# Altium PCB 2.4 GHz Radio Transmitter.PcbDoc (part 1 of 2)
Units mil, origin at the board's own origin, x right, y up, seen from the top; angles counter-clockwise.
Board outline 5905.26 x 4050.27 mil, 4 copper layers (Top Layer, GND, Power, Bottom Layer), stack 63.355 mil thick; 215 components, 108 nets, 659 pads, 107 vias.
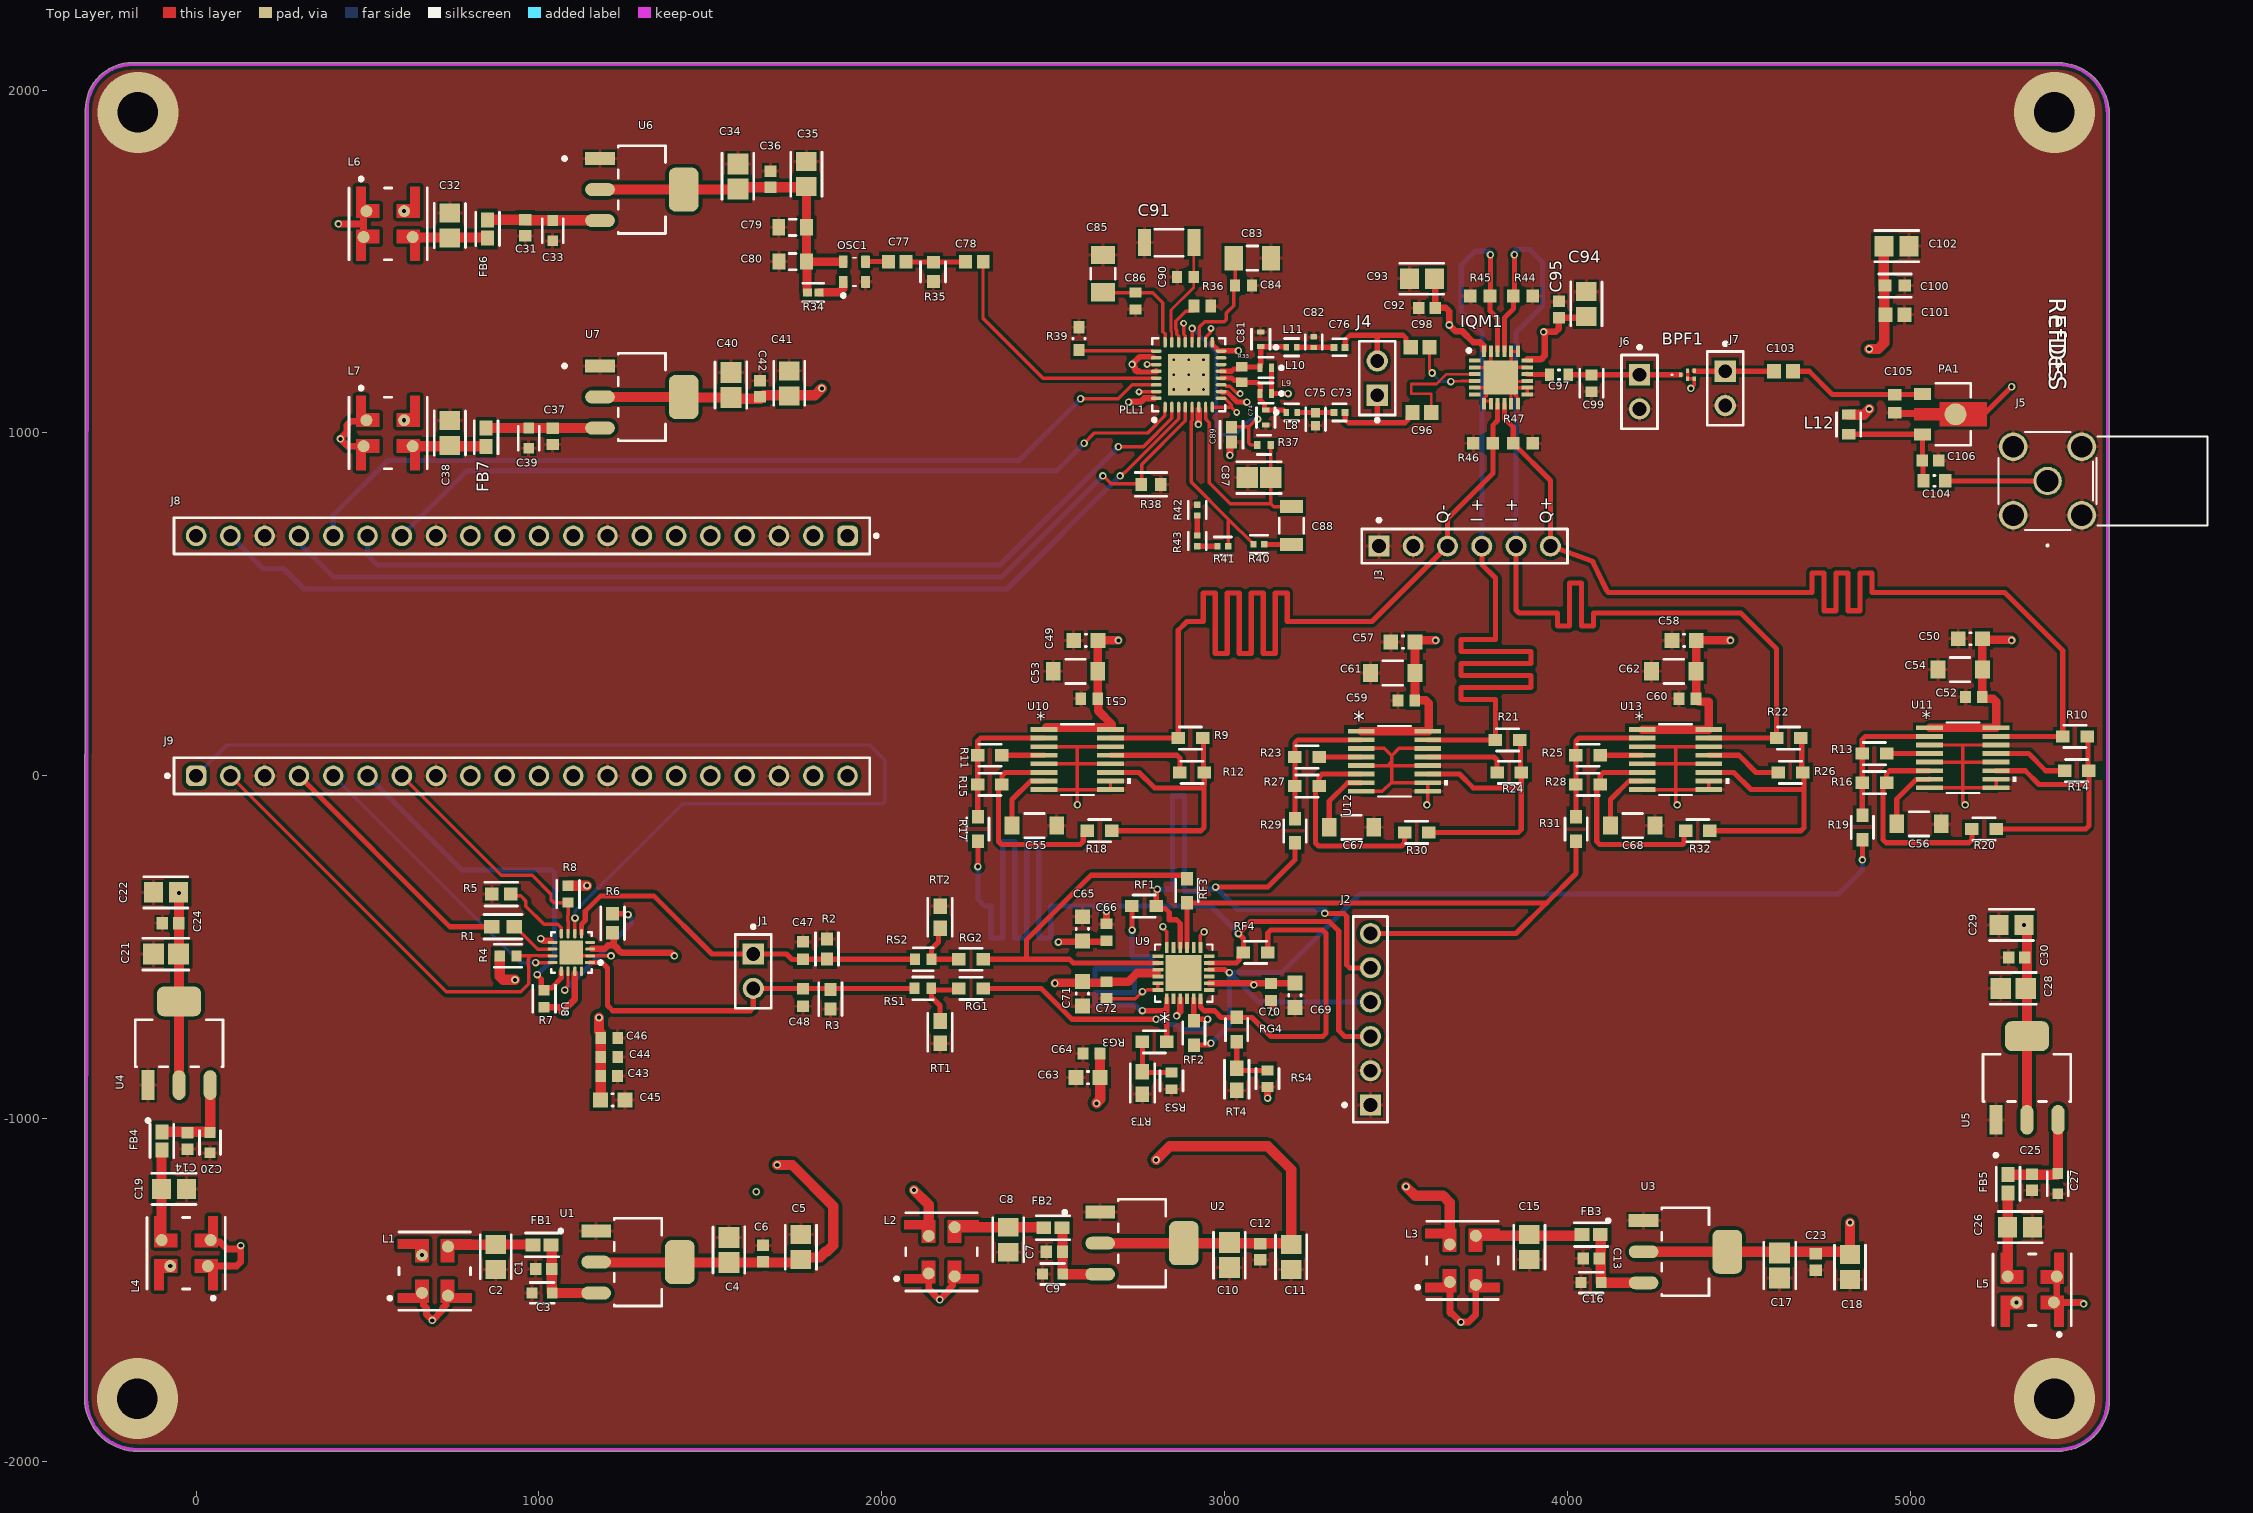
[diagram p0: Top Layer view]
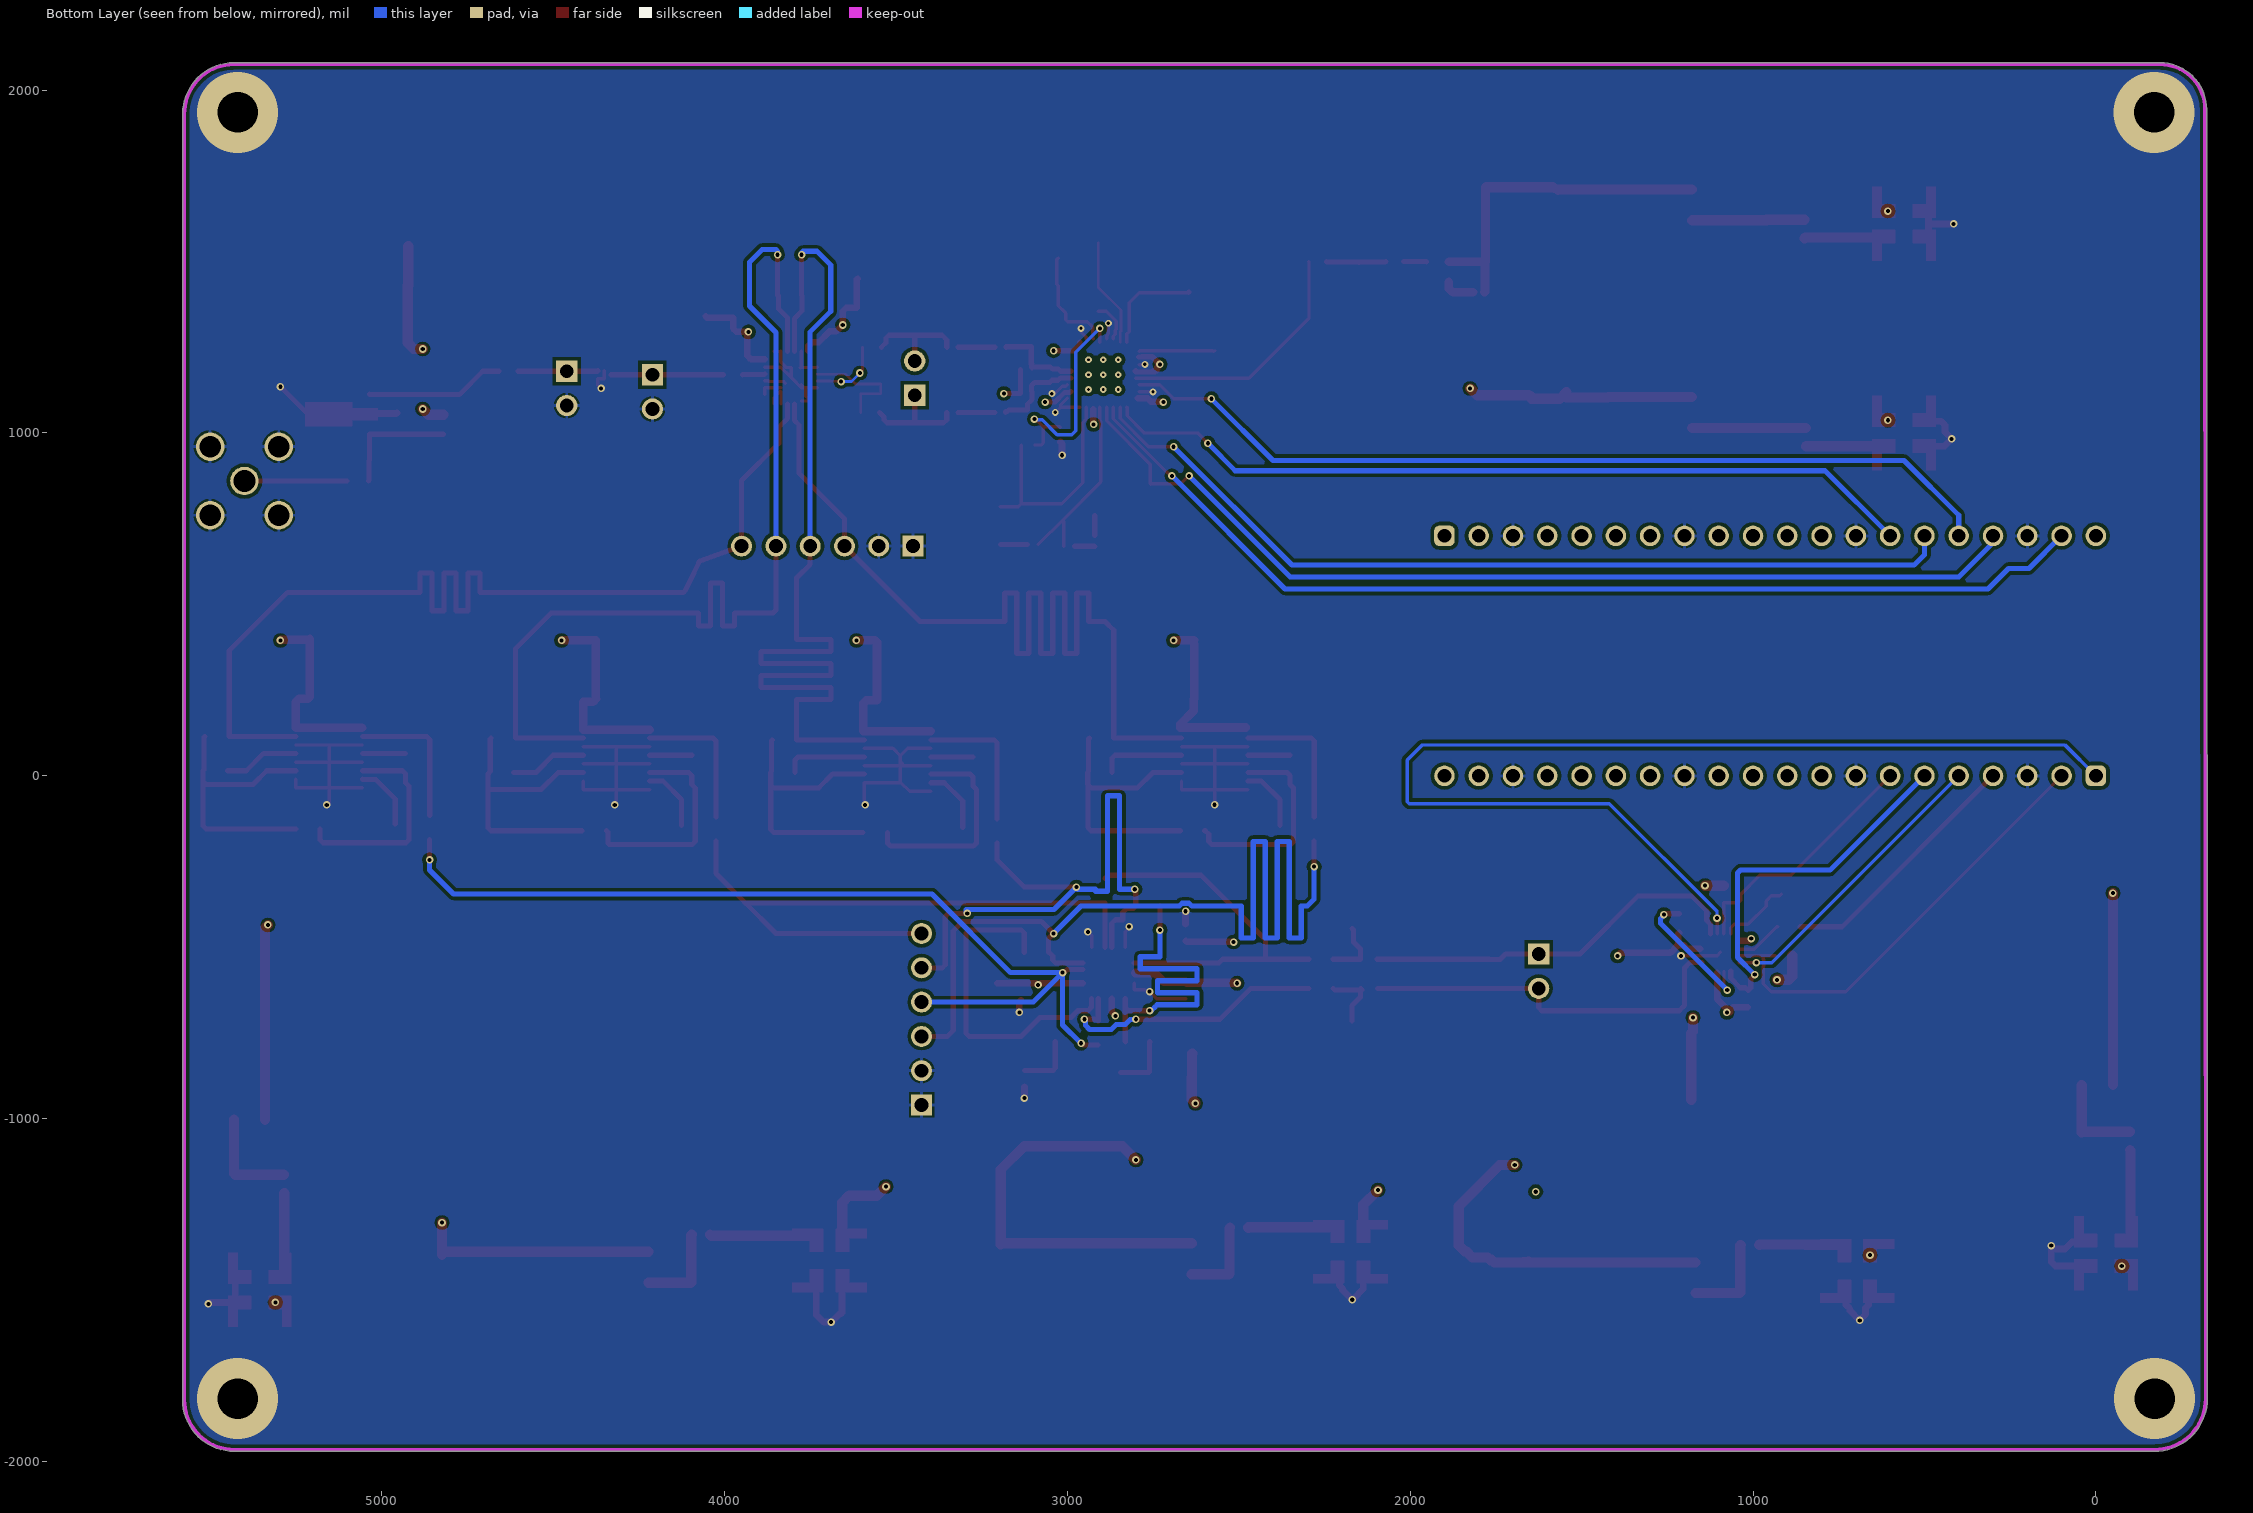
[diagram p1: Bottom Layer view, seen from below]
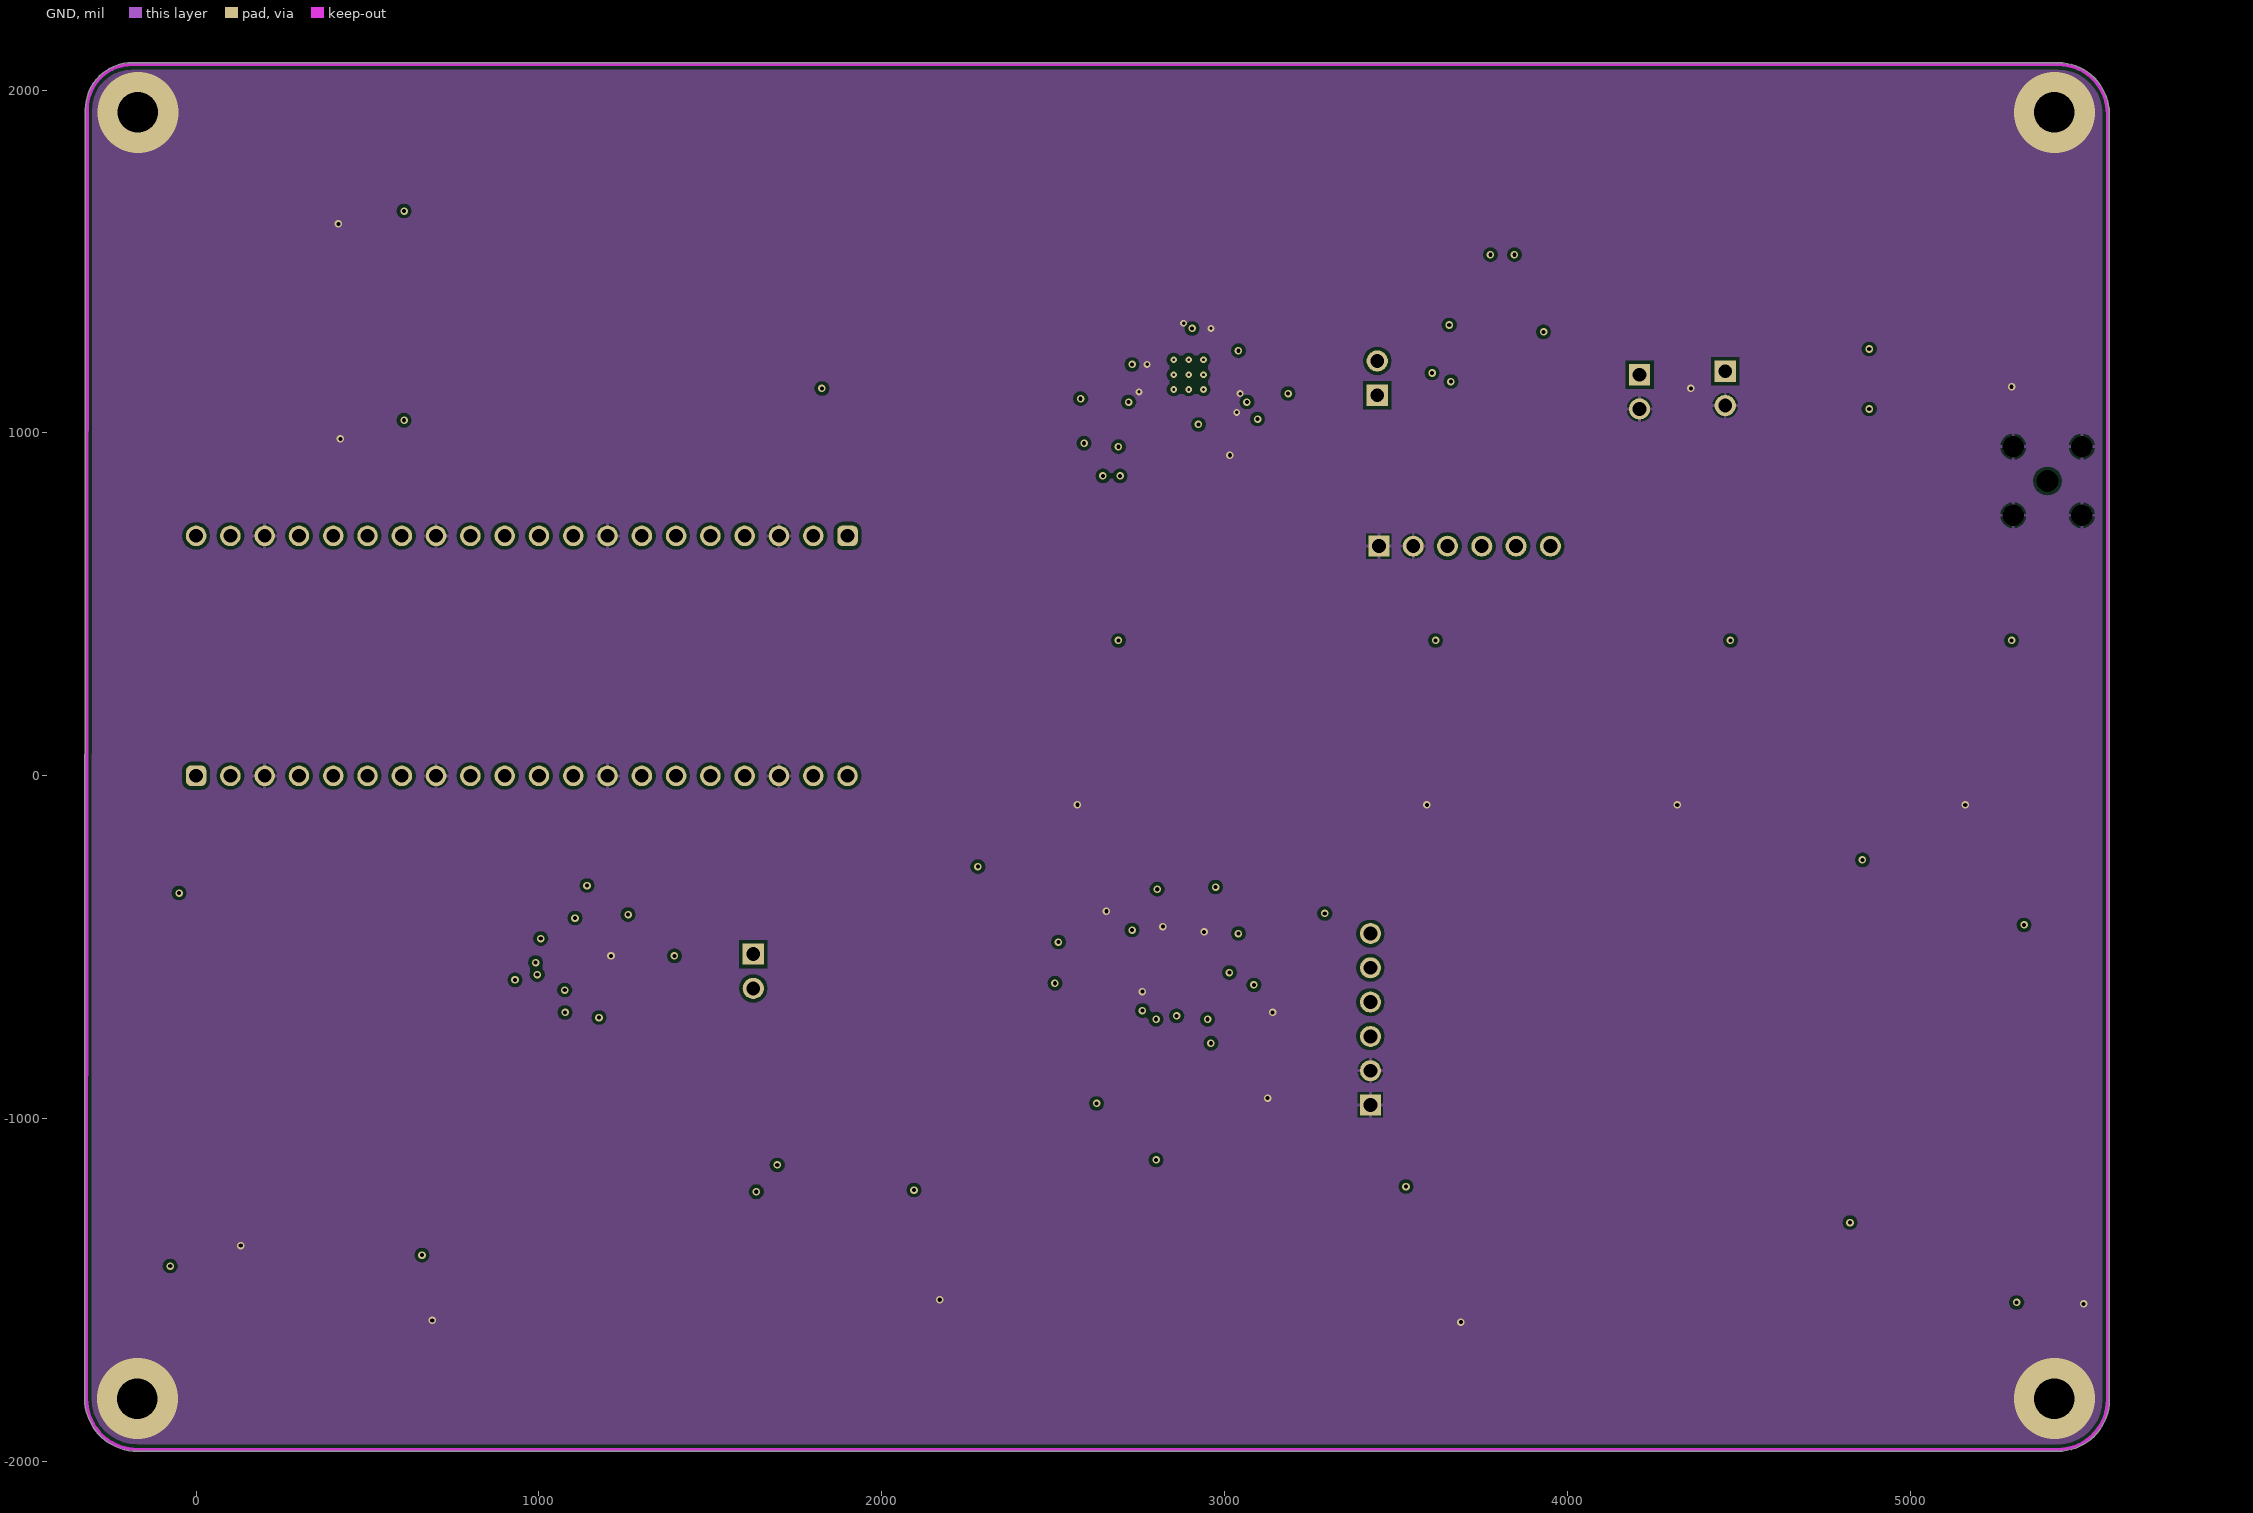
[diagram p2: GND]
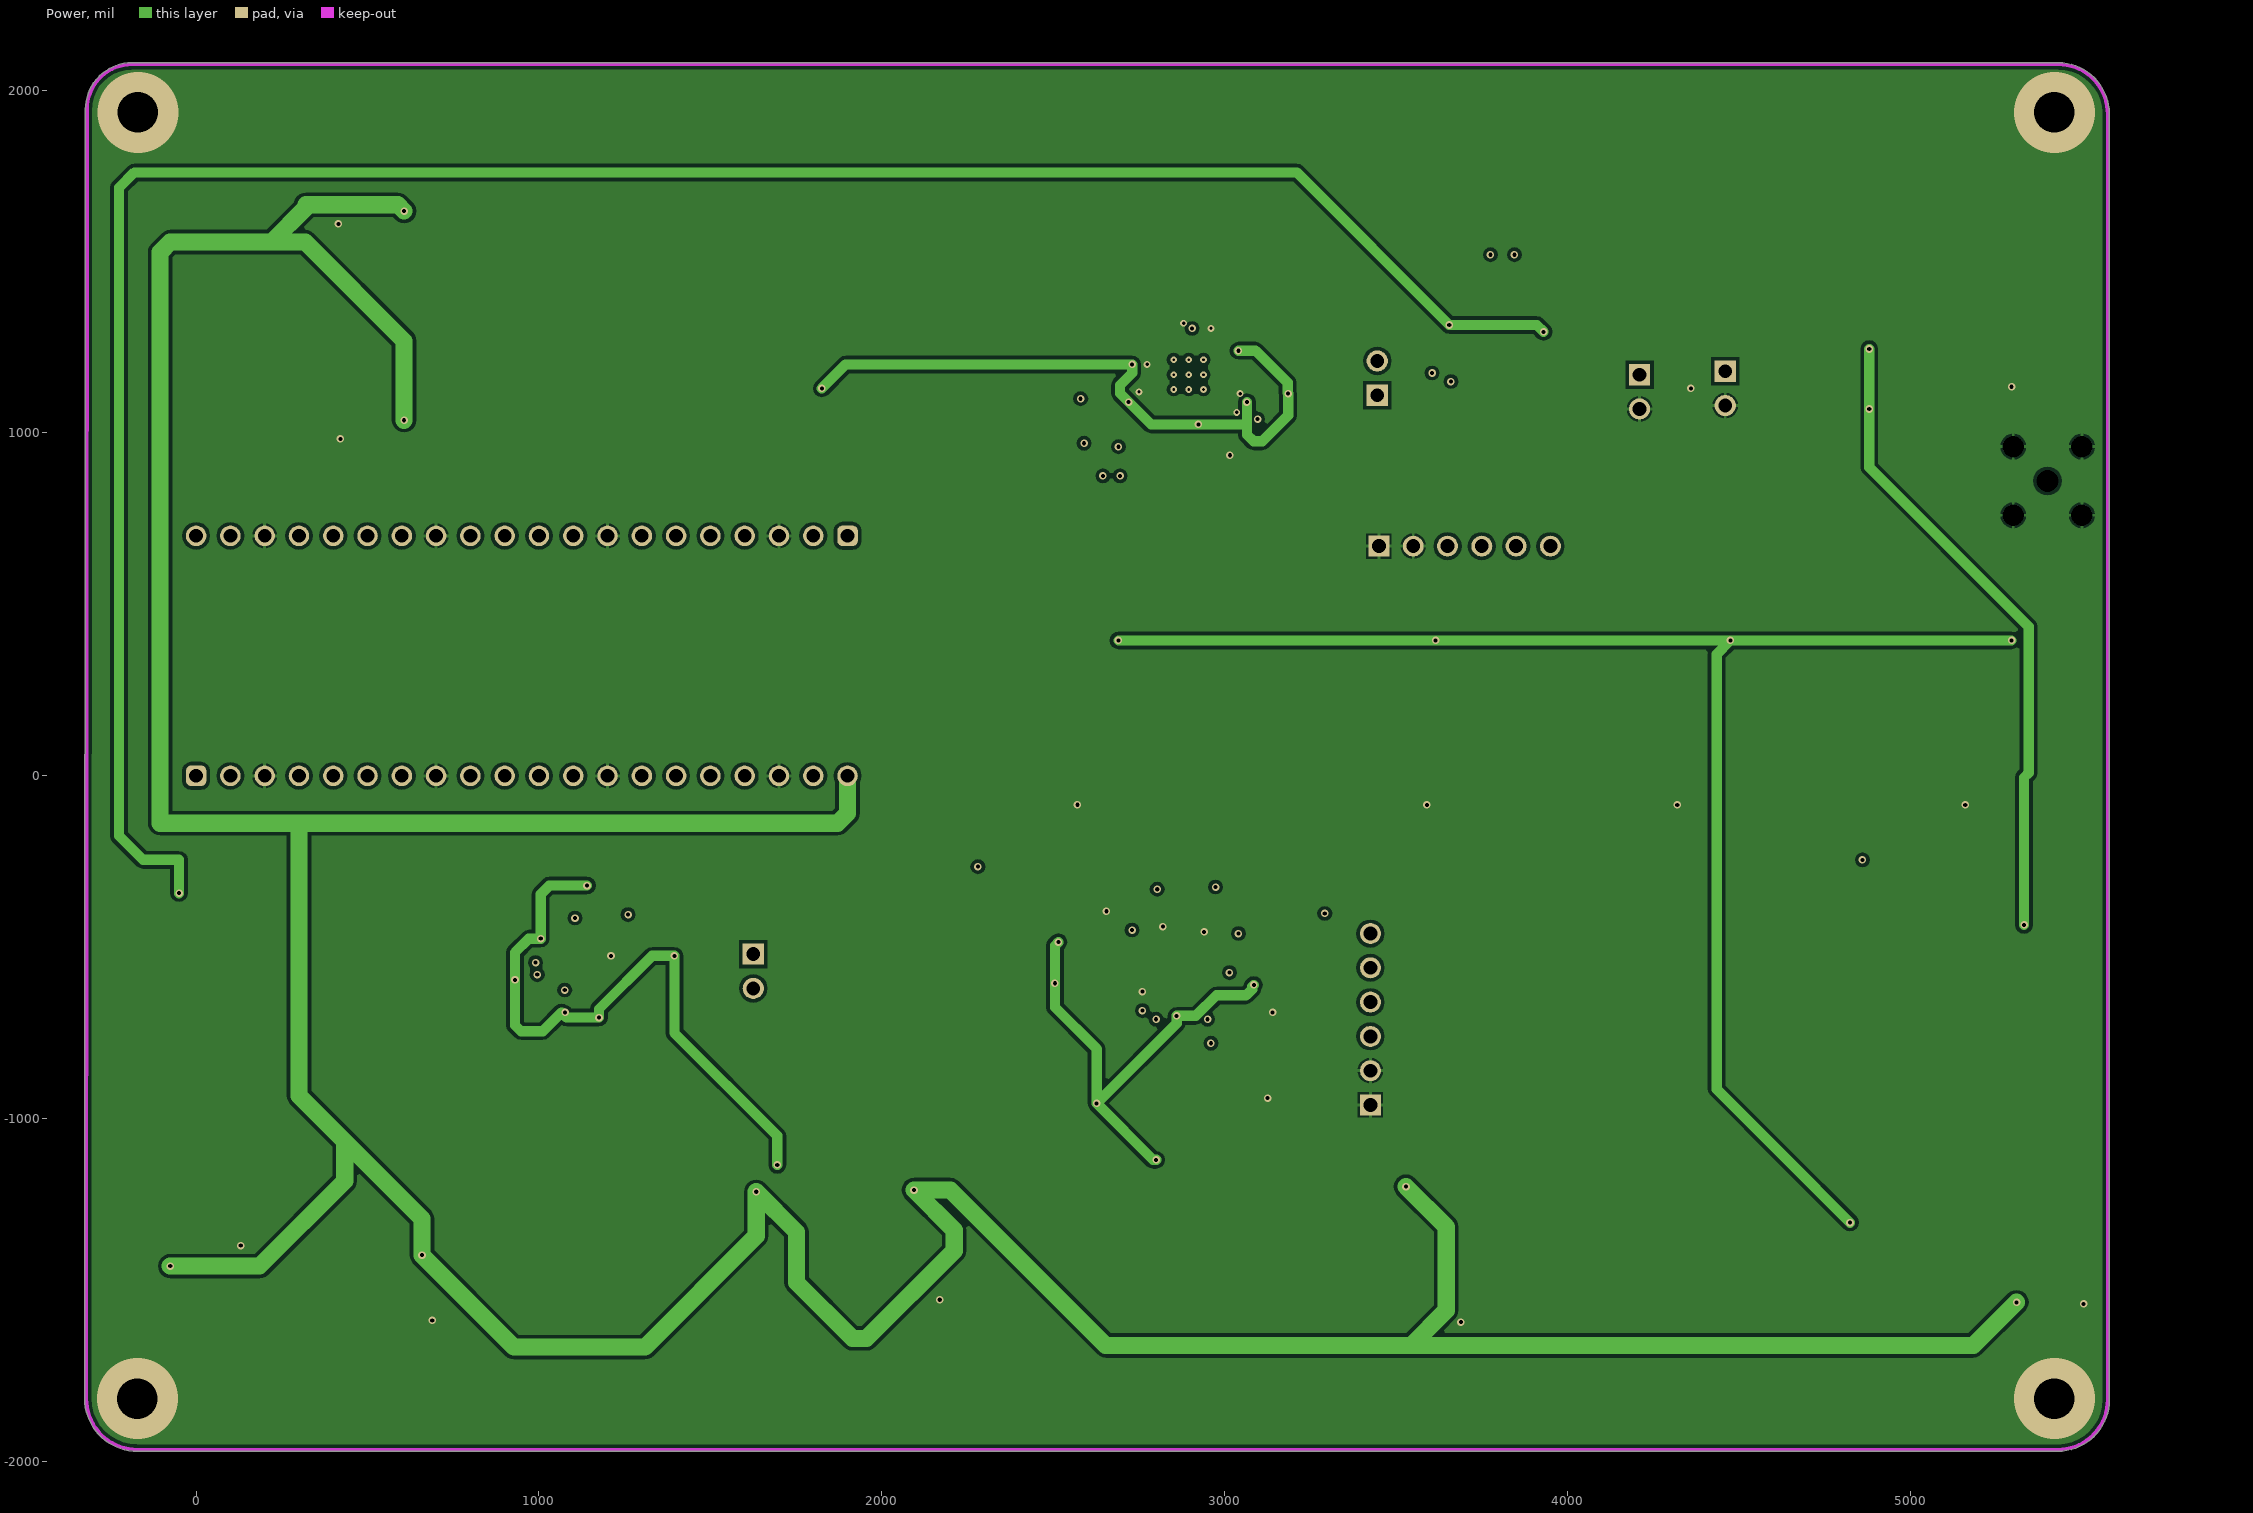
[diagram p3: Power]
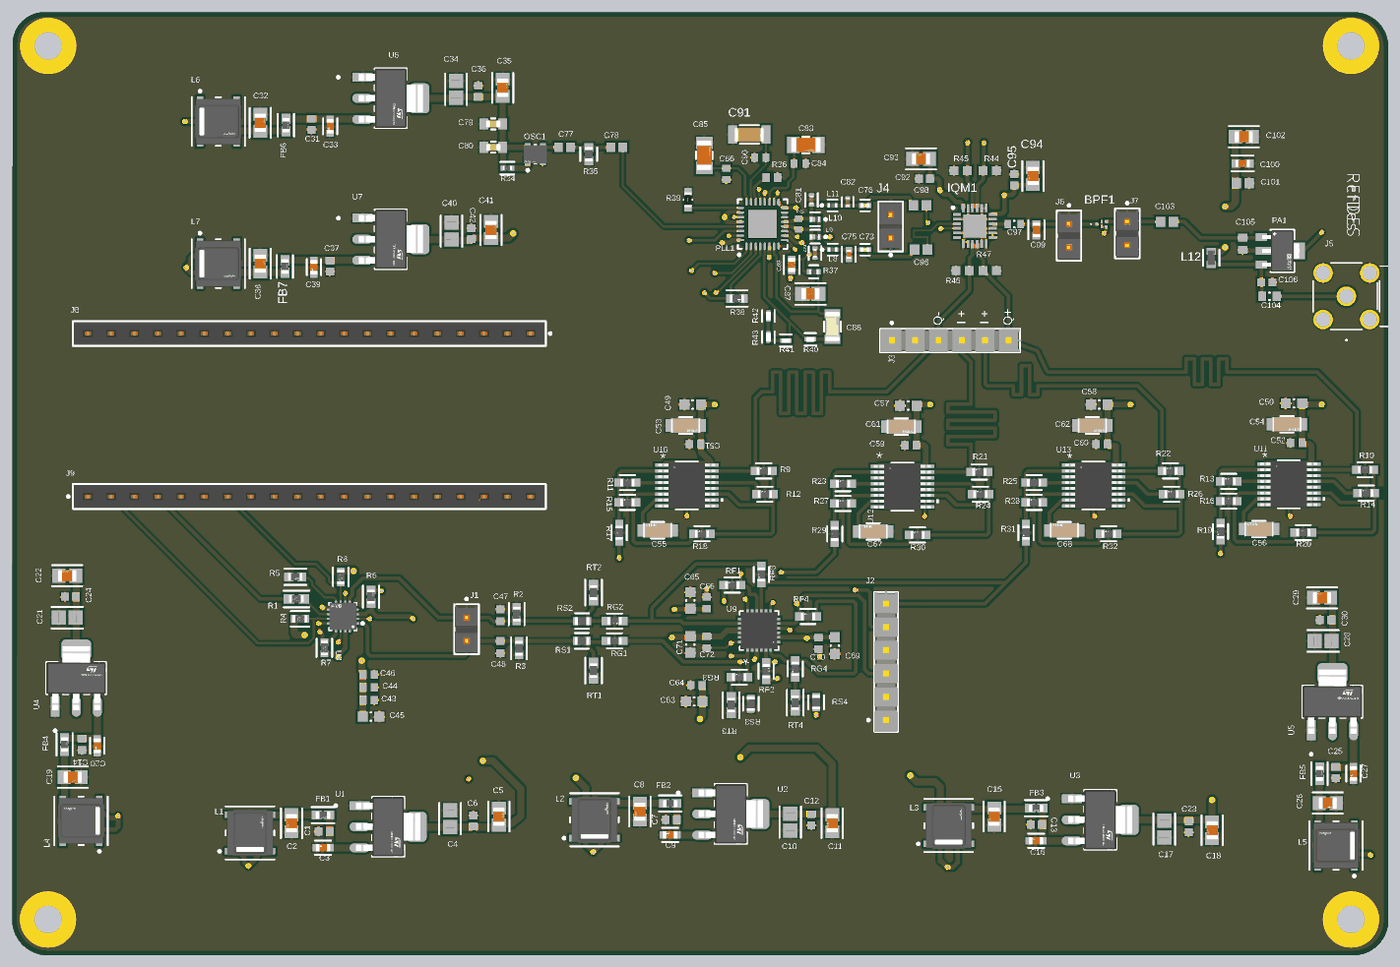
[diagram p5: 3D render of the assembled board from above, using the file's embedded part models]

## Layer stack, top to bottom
Top Solder: solder mask 1, Solder Resist, Dk 3.6
Top Layer: signal copper 1.378
Dielectric 1: prepreg 7.957, FR-4, Dk 3.61
GND: signal copper 1.378
Core: core 41.929, FR-4, Dk 4.4
Power: signal copper 1.378
Dielectric 2: prepreg 7.957, FR-4, Dk 3.61
Bottom Layer: signal copper 1.378
Bottom Solder: solder mask 1, Solder Resist, Dk 3.6

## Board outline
-325.02,-1816.32 -322.69,1944.12 cw(c-186.81,1944.11) -186.81,2080 5431.44,2080.02 5431.46,2080.01 cw(c5430.72,1930.72) 5580.02,1930.72 5580.04,1930 5580.25,-1819.6 cw(c5429.83,-1819.6) 5429.83,-1970.01 -171.08,-1970.26 cw(c-171.08,-1816.32)

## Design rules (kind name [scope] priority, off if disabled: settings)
BoardOutlineClearance [All] p1: gap=15 ignorepadtopadclearanceinfootprint=FALSE
Clearance "Clearance Polygons" [InPolygon] p1: gap=10 ignorepadtopadclearanceinfootprint=FALSE
Clearance [All] p2: gap=5 ignorepadtopadclearanceinfootprint=FALSE
ComponentClearance "HM-TRP & UFL" [InComponent('X1') vs InComponent('U1')] p1: gap=0 collisioncheckmode=3 verticalgap=0 showdistances=FALSE
ComponentClearance [All] p2: gap=1 collisioncheckmode=3 verticalgap=1 showdistances=FALSE
DiffPairsRouting [All] p1: maxlimit=393.7 minlimit=5 mostfreqgap=8 toplayer_minwidth=5 toplayer_maxwidth=15 toplayer_prefwidth=8 midlayer1_minwidth=5 midlayer1_maxwidth=15 midlayer1_prefwidth=8 midlayer2_minwidth=5 midlayer2_maxwidth=15 midlayer2_prefwidth=8 bottomlayer_minwidth=5 bottomlayer_maxwidth=15 bottomlayer_prefwidth=8 maxuncoupledlength=500
HoleSize [All] p1: absolutevalues=TRUE maxlimit=265 minlimit=10 maxpercent=80.000 minpercent=20.000
HoleToHoleClearance [All] p1: gap=10 allowstackedmicrovias=FALSE
MinimumAnnularRing [All] p1: minimumring=4
MinimumSolderMaskSliver [All] p1: minsoldermaskwidth=0
PlaneClearance [All] p1: clearance=10
PlaneConnect [All] p1: planeconnectstyle=Relief reliefexpansion=4 reliefentries=4 reliefconductorwidth=6 reliefairgap=6
PolygonConnect "Via connect style" [isVia] p1: connectstyle=Direct reliefconductorwidth=10 reliefentries=4 polygonreliefangle="90 Angle" airgapwidth=10
PolygonConnect [All] p2: connectstyle=Relief reliefconductorwidth=10 reliefentries=4 polygonreliefangle="90 Angle" airgapwidth=6
RoutingCorners [All] p1: cornerstyle=45-Degree minsetback=49.21 maxsetback=49.21
RoutingVias [All] p1: holewidth=12 width=22 viastyle="Through Hole" minholewidth=10 minwidth=18 maxholewidth=100 maxwidth=114
SilkToSilkClearance [All] p1: silktosilkclearance=0
SilkToSolderMaskClearance [IsPad] p1: minsilkscreentomaskgap=5 clearancetoexposedcopper=TRUE
SolderMaskExpansion [All] p1: expansion=2.5 istentingtop=FALSE
Width GND [InNet('GND')] p1: maxlimit=30 minlimit=10 preferedwidth=20
Width Power [InNetClass('Power')] p2: maxlimit=40 minlimit=20 preferedwidth=30
Width 3V3 [InNetClass('3V3')] p3: maxlimit=30 minlimit=10 preferedwidth=20
Width [All] p4: maxlimit=400 minlimit=6 preferedwidth=8
20 further rules are at their usual default settings.

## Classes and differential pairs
component class RF_FrontEnd: BPF1 C92 C93 C94 C95 C96 C97 C98 C99 C100 C101 C102 C103 C104 C105 C106 IQM1 J5 J6 J7 L12 PA1 R44 R45 R46 R47
component class PowerFilterLDO: C1 C2 C3 C4 C5 C6 C7 C8 C9 C10 C11 C12 C13 C14 C15 C16 C17 C18 C19 C20 C21 C22 C23 C24 C25 C26 C27 C28 C29 C30 C31 C32 C33 C34 C35 C36 C37 C38 C39 C40 C41 C42 FB1 FB2 FB3 FB4 FB5 FB6 FB7 L1 L2 L3 L4 L5 L6 L7 U1 U2 U3 U4 U5 U6 U7
component class FrequencySynthesis: C73 C74 C75 C76 C77 C78 C79 C80 C81 C82 C83 C84 C85 C86 C87 C88 C89 C90 C91 J4 L8 L9 L10 L11 OSC1 PLL1 R33 R34 R35 R36 R37 R38 R39 R40 R41 R42 R43
component class DSP: J8 J9
component class AnalogBaseband: C43 C44 C45 C46 C47 C48 C49 C50 C51 C52 C53 C54 C55 C56 C57 C58 C59 C60 C61 C62 C63 C64 C65 C66 C67 C68 C69 C70 C71 C72 J1 J2 J3 R1 R2 R3 R4 R5 R6 R7 R8 R9 R10 R11 R12 R13 R14 R15 R16 R17 R18 R19 R20 R21 R22 R23 R24 R25 R26 R27 R28 R29 R30 R31 R32 RF1 RF2 RF3 RF4 RG1 RG2 RG3 RG4 RS1 RS2 RS3 RS4 RT1 RT2 RT3 RT4 U8 U9 U10 U11 U12 U13
differential pair QOUT: +QOUT_P -QOUT_N
differential pair QIN: +QIN_P -QIN_N
differential pair LO3: +LO3_P -LO3_N
differential pair LO2: +LO2_P -LO2_N
differential pair IOUT: +IOUT_P -IOUT_N
differential pair IN2: +IN2_P -IN2_N
differential pair IN1: +IN1_P -IN1_N
differential pair LO: +LO_P -LO_N
differential pair LO1: +LO1_P -LO1_N
differential pair BBQ: +BBQ_P -BBQ_N
differential pair BBI: +BBI_P -BBI_N

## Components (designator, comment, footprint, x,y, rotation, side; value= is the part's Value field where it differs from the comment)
BPF1 "DEA142450BT-3028A1" DEA142450BT3028A1 4350,1170 r0 top
C1 "0.1 uF" CAPC1608X95X40LL15T15 1013.82,-1438.13 r0 top
C2 "10 uF" FP-GCM21B-0_15-IPC_A 873.82,-1403.13 r270 top value=10µF
C3 "1 uF" FP-VJ0603Y105KXJCW1BC-MFG 1009.29,-1508.13 r180 top
C4 "4.7 uF" FP-GCJ21B-0_3-IPC_A 1553.82,-1383.13 r90 top
C5 "10 uF" FP-GCM21B-0_15-IPC_A 1763.82,-1374.59 r90 top value=10µF
C6 "0.1 uF" CAPC1608X95X40LL15T15 1653.82,-1393.13 r270 top
C7 "0.1 uF" CAPC1608X95X40LL15T15 2503.35,-1388.13 r0 top
C8 "10 uF" FP-GCM21B-0_15-IPC_A 2368.82,-1353.13 r270 top value=10µF
C9 "1 uF" FP-VJ0603Y105KXJCW1BC-MFG 2498.35,-1453.13 r180 top
C10 "4.7 uF" FP-GCJ21B-0_3-IPC_A 3013.82,-1398.13 r270 top
C11 "10 uF" FP-GCM21B-0_15-IPC_A 3193.82,-1403.13 r270 top value=10µF
C12 "0.1 uF" CAPC1608X95X40LL15T15 3103.82,-1388.13 r90 top
C13 "0.1 uF" CAPC1608X95X40LL15T15 4068.82,-1408.13 r0 top
C14 "0.1 uF" CAPC1608X95X40LL15T15 -24.69,-1065 r90 top
C15 "10 uF" FP-GCM21B-0_15-IPC_A 3888.82,-1374.59 r270 top value=10µF
C16 "1 uF" FP-VJ0603Y105KXJCW1BC-MFG 4068.82,-1478.13 r180 top
C17 "4.7 uF" FP-GCJ21B-0_3-IPC_A 4618.82,-1428.13 r270 top
C18 "10 uF" FP-GCM21B-0_15-IPC_A 4823.82,-1433.13 r270 top value=10µF
C19 "10 uF" FP-GCM21B-0_15-IPC_A -64.69,-1205 r0 top value=10µF
C20 "1 uF" FP-VJ0603Y105KXJCW1BC-MFG 40.31,-1070 r270 top
C21 "4.7 uF" FP-GCJ21B-0_3-IPC_A -88.25,-520 r180 top
C22 "10 uF" FP-GCM21B-0_15-IPC_A -88.22,-340 r180 top value=10µF
C23 "0.1 uF" CAPC1608X95X40LL15T15 4723.82,-1418.13 r90 top
C24 "0.1 uF" CAPC1608X95X40LL15T15 -74.69,-430 r0 top
C25 "0.1 uF" CAPC1608X95X40LL15T15 5355,-1185 r90 top
C26 "10 uF" FP-GCM21B-0_15-IPC_A 5320,-1316.17 r0 top value=10µF
C27 "1 uF" FP-VJ0603Y105KXJCW1BC-MFG 5430,-1189.53 r270 top
C28 "4.7 uF" FP-GCJ21B-0_3-IPC_A 5300,-620 r180 top
C29 "10 uF" FP-GCM21B-0_15-IPC_A 5295,-435 r180 top value=10µF
C30 "0.1 uF" CAPC1608X95X40LL15T15 5310,-530 r0 top
C31 "0.1 uF" CAPC1608X95X40LL15T15 960,1598.62 r90 top
C32 "10 uF" FP-GCM21B-0_15-IPC_A 740,1605 r90 top value=10µF
C33 "1 uF" FP-VJ0603Y105KXJCW1BC-MFG 1040,1590 r270 top
C34 "4.7 uF" FP-GCJ21B-0_3-IPC_A 1580,1748.57 r90 top
C35 "10 uF" FP-GCM21B-0_15-IPC_A 1780,1755 r90 top value=10µF
C36 "0.1 uF" CAPC1608X95X40LL15T15 1675,1740 r270 top
C37 "0.1 uF" CAPC1608X95X40LL15T15 1040,990 r90 top
C38 "10 uF" FP-GCM21B-0_15-IPC_A 740,1000 r90 top value=10µF
C39 "1 uF" FP-VJ0603Y105KXJCW1BC-MFG 970,985 r270 top
C40 "4.7 uF" FP-GCJ21B-0_3-IPC_A 1560,1140 r90 top
C41 "10 uF" FP-GCM21B-0_15-IPC_A 1730,1145 r90 top value=10µF
C42 "0.1 uF" CAPC1608X95X40LL15T15 1645,1128.62 r270 top
C43 "0.1uF" CAPC1608X87X35LL15T15 1204.61,-875 r180 top
C44 "0.1uF" CAPC1608X87X35LL15T15 1205,-820 r180 top
C45 "10uF" CAPC0603(1608)100_M 1215,-945 r180 top
C46 "0.1uF" CAPC1608X87X35LL15T15 1205,-765 r180 top
C47 "" CAPC1608X90X35LL15T15 1770,-510 r270 top
C48 "" CAPC1608X90X35LL15T15 1770,-646.38 r90 top
C49 "10uF" CAPC0603(1608)100_M 2595,395 r0 top
C50 "10uF" CAPC0603(1608)100_M 5175,400 r0 top
C51 "0.1uF" CAPC1608X87X35LL15T15 2605,225 r0 top
C52 "0.1uF" CAPC1608X87X35LL15T15 5185,230 r0 top
C53 "CGA5L2C0G1H104J160AA" FP-CGA5L-MFG 2565,305 r180 top
C54 "CGA5L2C0G1H104J160AA" FP-CGA5L-MFG 5145,310 r180 top
C55 "CGA5L2C0G1H104J160AA" FP-CGA5L-MFG 2445,-145 r0 top
C56 "CGA5L2C0G1H104J160AA" FP-CGA5L-MFG 5025,-140 r0 top
C57 "10uF" CAPC0603(1608)100_M 3520,390 r0 top
C58 "10uF" CAPC0603(1608)100_M 4340,395 r0 top
C59 "0.1uF" CAPC1608X87X35LL15T15 3530,220 r0 top
C60 "0.1uF" CAPC1608X87X35LL15T15 4350,225 r0 top
C61 "CGA5L2C0G1H104J160AA" FP-CGA5L-MFG 3490,300 r180 top
C62 "CGA5L2C0G1H104J160AA" FP-CGA5L-MFG 4310,305 r180 top
C63 "10uF" CAPC0603(1608)100_M 2601.3,-880 r0 top
C64 "0.1uF" CAPC1608X87X35LL15T15 2611.3,-810 r0 top
C65 "10uF" CAPC0603(1608)100_M 2585,-446.3 r270 top
C66 "0.1uF" CAPC1608X87X35LL15T15 2655,-456.3 r270 top
C67 "CGA5L2C0G1H104J160AA" FP-CGA5L-MFG 3370,-150 r0 top
C68 "CGA5L2C0G1H104J160AA" FP-CGA5L-MFG 4190,-145 r0 top
C69 "10uF" CAPC0603(1608)100_M 3205,-640 r90 top
C70 "0.1uF" CAPC1608X87X35LL15T15 3135,-630.39 r90 top
C71 "10uF" CAPC0603(1608)100_M 2585,-635.43 r90 top
C72 "0.1uF" CAPC1608X87X35LL15T15 2655,-625 r90 top
C73 "1nF" FP-C0402C102K4RAC7411-MFG 3335,1060 r0 top
C74 "2.2pF" FP-CGA2B-IPC_B 3120,1045 r270 top
C75 "1.5pF" FP-GCM155-0_05-IPC_A 3265,1040 r270 top
C76 "1nF" FP-C0402C102K4RAC7411-MFG 3335,1250 r0 top
C77 "1nF" CAPC1608X95X40NL15T15 2045,1500 r0 top
C78 "1nF" CAPC1608X95X40NL15T15 2270,1500 r0 top
C79 "1nF" FP-CGA3E-0_3-0_1-IPC_A 1739.65,1600 r180 top
C80 "1nF" FP-CGA3E-0_3-0_1-IPC_A 1740,1500 r180 top
C81 "2.2pF" FP-CGA2B-IPC_B 3105,1273.35 r90 top
C82 "1.5pF" FP-CGA2B-MFG 3260,1265 r90 top
C83 "100nF" FP-GRM31C-0_2-e0_3_0_8-IPC_B 3080.84,1510 r0 top
C84 "10pF" CAPC1608X92X38LL15T08 3055,1430 r180 top
C85 "100nF" FP-GRM31C-0_2-e0_3_0_8-IPC_B 2645,1465 r90 top
C86 "10pF" CAPC1608X92X38LL15T08 2740,1385 r90 top
C87 "2.7nF" FP-C2012-125-0_2-IPC_A 3100,870 r180 top
C88 "39nF" FP-C1206C-EB-MFG 3195,730 r270 top value="39,000 pF"
C89 "1.2nF" FP-C1608-080-0_1-IPC_C 3020,995 r270 top
C90 "10pF" CAPC1608X92X38LL15T08 2885,1455 r0 top
C91 "100nF" FP-CGA5L-0_3-0_1-IPC_A 2838.15,1555 r180 top
C92 "0.1 uF" CAPC1608X95X40LL15T15 3590,1365 r0 top
C93 "10 uF" FP-GCM21B-0_15-IPC_A 3575,1450 r180 top value=10µF
C94 "10 uF" FP-GCM21B-0_15-IPC_A 4055,1376.47 r270 top value=10µF
C95 "0.1 uF" CAPC1608X95X40LL15T15 3975,1360 r270 top
C96 "12 pF" CAPC1608X95X40ML15T15 3575,1060 r0 top
C97 "6.8 pF" CAPC0603(1608)100_L 3975,1170 r0 top value=6.8pF
C98 "12 pF" CAPC1608X95X40ML15T15 3570,1250 r0 top
C99 "0.2 pF" FP-GQM187-0_15-IPC_C 4070,1145 r270 top
C100 "10 nF" FP-GRM188-0_1-e0_2_0_5-IPC_B 4955,1430 r0 top
C101 "12 pF" CAPC1608X95X40ML15T15 4955,1345 r180 top
C102 "10 uF" FP-GCM21B-0_15-IPC_A 4960,1545 r0 top value=10µF
C103 "12 pF" CAPC1608X95X40ML15T15 4630,1180 r0 top
C104 "2.2 pF" CAPC0603(1608)100_N 5070,860 r0 top value=2.2pF
C105 "1.2 pF" CAPC1608X92X38NL15T08 4955,1085 r90 top
C106 "1 pF" CAPC1608X95X40LL15T15 5058.5,920 r180 top
FB1 "" FP-BLM18-0_15-t0_8-IPC_B 1008.82,-1368.13 r0 top
FB2 "" FP-BLM18-0_15-t0_8-IPC_B 2498.82,-1318.13 r0 top
FB3 "" FP-BLM18-0_15-t0_8-IPC_B 4068.82,-1338.13 r0 top
FB4 "" FP-BLM18-0_15-t0_8-IPC_B -99.69,-1065 r90 top
FB5 "" FP-BLM18-0_15-t0_8-IPC_B 5285,-1190 r90 top
FB6 "" FP-BLM18-0_15-t0_8-IPC_B 850,1595 r90 top
FB7 "" FP-BLM18-0_15-t0_8-IPC_B 845.59,987.72 r90 top
IQM1 "TRF3705IRGET" QFN50P400X400X100-25N-D 3805.79,1161.77 r0 top
J1 "TSW-102-07-G-S" FP-TSW-102-07-G-S-MFG 1625,-570 r270 top
J2 "TSW-106-07-S-S" SMTC-TSW-106-07-S-S_V 3425,-710 r90 top
J3 "TSW-106-07-S-S" SMTC-TSW-106-07-S-S_V 3700,670 r0 top
J4 "TSW-102-07-L-S" FP-TSW-102-07-L-S-MFG 3445,1160 r90 top
J5 "SMA-J-P-H-RA-TH1" CONN_SMA-J-P-H-RA-TH1_SAI 5400,860 r270 top
J6 "TSW-102-07-G-S" FP-TSW-102-07-G-S-MFG 4210,1120 r270 top
J7 "TSW-102-07-G-S" FP-TSW-102-07-G-S-MFG 4460,1130 r270 top
J8 "61302011821" 61302011821 950,700 r180 top
J9 "61302011821" 61302011821 950,0 r0 top
L1 "" FP-DLW5BS-MFG 695.98,-1444.63 r0 top value=500Ω
L2 "" FP-DLW5BS-MFG 2173.82,-1388.13 r0 top value=500Ω
L3 "" FP-DLW5BS-MFG 3693.82,-1413.13 r0 top value=500Ω
L4 "" FP-DLW5BS-MFG -29.1,-1392.6 r90 top value=500Ω
L5 "" FP-DLW5BS-MFG 5355.33,-1498.77 r90 top value=500Ω
L6 "" FP-DLW5BS-MFG 560,1610 r270 top value=500Ω
L7 "" FP-DLW5BS-MFG 560,1000 r270 top value=500Ω
L8 "3.6nH" FP-LQG15HH_02-MFG 3195.75,1060 r0 top
L9 "7.5nH" FP-LQG15WH_02-MFG 3120,1115 r180 top
L10 "7.5nH" FP-LQG15WH_02-MFG 3120,1190 r180 top
L11 "3.6nH" FP-LQG15HH_02-MFG 3195,1250 r0 top
L12 "15 nH" FP-LQW18CA_00-MFG 4820,1025 r90 top
OSC1 "LMK6CE10000DDLFT" DLF0004A_MFG 1920,1470 r90 top
PA1 "ADL5320ARKZ-R7" FP-RK-3-MFG 5125.26,1054.57 r270 top
PLL1 "ADF4350BCPZ-RL7" ADI-CP-32-2_L 2895,1170 r90 top
R1 "CRGCQ0603F22R" FP-CRGCQ0603-IPC_A 895,-440 r0 top
R2 "" FP-CR0603-IPC_B 1840,-505 r270 top
R3 "" FP-CR0603-IPC_B 1850,-651.38 r90 top
R4 "10K" FP-CRGCQ0603-IPC_C 910,-525 r0 top value=10KΩ
R5 "0" FP-RMCF0603-IPC_B 890,-345 r0 top
R6 "0" FP-RMCF0603-IPC_B 1215,-430 r90 top
R7 "10K" FP-CRGCQ0603-IPC_C 1015,-650 r270 top value=10KΩ
R8 "10K" FP-CRGCQ0603-IPC_C 1085,-345 r270 top value=10KΩ
R9 "CPF0603B120KE1" FP-CPF0603-MFG 2900,110 r0 top
R10 "CPF0603B120KE1" FP-CPF0603-MFG 5480,115 r0 top
R11 "CPF0603B120KE1" FP-CPF0603-MFG 2315,60 r0 top
R12 "CPF0603B120KE1" FP-CPF0603-MFG 2905,10 r0 top
R13 "CPF0603B120KE1" FP-CPF0603-MFG 4895,65 r0 top
R14 "CPF0603B120KE1" FP-CPF0603-MFG 5485,15 r0 top
R15 "CPF0603B120KE1" FP-CPF0603-MFG 2315,-25 r0 top
R16 "CPF0603B120KE1" FP-CPF0603-MFG 4895,-20 r0 top
R17 "CPF0603B120KE1" FP-CPF0603-MFG 2280,-155.43 r90 top
R18 "CPF0603B120KE1" FP-CPF0603-MFG 2635,-160 r0 top
R19 "CPF0603B120KE1" FP-CPF0603-MFG 4860,-150.43 r90 top
R20 "CPF0603B120KE1" FP-CPF0603-MFG 5215,-155 r0 top
R21 "CPF0603B120KE1" FP-CPF0603-MFG 3825,105 r0 top
R22 "CPF0603B120KE1" FP-CPF0603-MFG 4645,110 r0 top
R23 "CPF0603B120KE1" FP-CPF0603-MFG 3240,55 r0 top
R24 "CPF0603B120KE1" FP-CPF0603-MFG 3830,10 r0 top
R25 "CPF0603B120KE1" FP-CPF0603-MFG 4060,60 r0 top
R26 "CPF0603B120KE1" FP-CPF0603-MFG 4650,10 r0 top
R27 "CPF0603B120KE1" FP-CPF0603-MFG 3240,-30 r0 top
R28 "CPF0603B120KE1" FP-CPF0603-MFG 4060,-25 r0 top
R29 "CPF0603B120KE1" FP-CPF0603-MFG 3205,-160.43 r90 top
R30 "CPF0603B120KE1" FP-CPF0603-MFG 3560,-165 r0 top
R31 "CPF0603B120KE1" FP-CPF0603-MFG 4025,-155.43 r90 top
R32 "CPF0603B120KE1" FP-CPF0603-MFG 4380,-160 r0 top
R33 "100" RESC1609X50X30LL10T20 3050,1170 r270 top
R34 "10k" FP-CRG0402-IPC_B 1800,1410 r0 top
R35 "51" FP-CRCW0603-e3-IPC_B 2150,1470 r270 top
R36 "4.7k" RESC1609X50X30NL10T20 2935,1370 r0 top
R37 "680" FP-RT0402-MFG 3115,965 r180 top value=680Ω
R38 "10k" FP-MCT0603-IPC_B 2785,850 r0 top
R39 "100" FP-SR0603-MFG 2575,1275 r90 top value=100Ω
R40 "360" FP-CRCW0402-e3-IPC_C 3100,675 r180 top
R41 "360" FP-CRCW0402-e3-IPC_C 2995,670 r180 top
R42 "360" FP-CRCW0402-e3-IPC_C 2920,775 r90 top
R43 "360" FP-CRCW0402-e3-IPC_C 2920,685 r90 top
R44 "49.9 Ohm" RESC1609X55X30NL10T20 3870,1400 r0 top value=49.9Ω
R45 "49.9 Ohm" RESC1609X55X30NL10T20 3745,1400 r180 top value=49.9Ω
R46 "49.9 Ohms" RESC1609X55X30NL10T20 3753.54,970 r180 top value=49.9Ω
R47 "49.9 Ohms" RESC1609X55X30NL10T20 3870,970 r180 top value=49.9Ω
RF1 "6-1879336-2" FP-CPF0603-MFG 2765,-380 r0 top
RF2 "6-1879336-2" FP-CPF0603-MFG 2910,-750 r270 top
RF3 "6-1879336-2" FP-CPF0603-MFG 2890,-335 r90 top
RF4 "6-1879336-2" FP-CPF0603-MFG 3090,-515 r0 top
RG1 "6-1879336-2" FP-CPF0603-MFG 2260,-620 r0 top
RG2 "6-1879336-2" FP-CPF0603-MFG 2260,-535 r180 top
RG3 "6-1879336-2" FP-CPF0603-MFG 2795,-775.77 r0 top
RG4 "6-1879336-2" FP-CPF0603-MFG 3035,-740 r90 top
RS1 "CRCW060350R0FKEA" FP-CRCW0603-e3-IPC_C 2120,-620 r0 top
RS2 "CRCW060350R0FKEA" FP-CRCW0603-e3-IPC_C 2120.77,-535 r180 top
RS3 "CRCW060350R0FKEA" FP-CRCW0603-e3-IPC_C 2845,-890 r90 top
RS4 "CRCW060350R0FKEA" FP-CRCW0603-e3-IPC_C 3125,-883.33 r90 top
RT1 "CR0603-FX-52R3ELF" FP-CR0603-IPC_A 2170,-747.56 r90 top
RT2 "CR0603-FX-52R3ELF" FP-CR0603-IPC_A 2170,-412.44 r270 top
RT3 "CR0603-FX-52R3ELF" FP-CR0603-IPC_A 2760,-895.77 r90 top
RT4 "CR0603-FX-52R3ELF" FP-CR0603-IPC_A 3035,-885 r90 top
U1 "LDL1117S33R" FP-SOT223-0046067-IPC_A 1288.82,-1418.13 r0 top
U2 "LDL1117S33R" FP-SOT223-0046067-IPC_A 2758.82,-1363.13 r0 top
U3 "LDL1117S33R" FP-SOT223-0046067-IPC_A 4343.82,-1388.13 r0 top
U4 "LDL1117S33R" FP-SOT223-0046067-IPC_A -49.69,-780 r90 top
U5 "LDL1117S33R" FP-SOT223-0046067-IPC_A 5340,-881.17 r90 top
U6 "LDL1117S33R" FP-SOT223-0046067-IPC_A 1300,1710 r0 top
U7 "LDL1117S33R" FP-SOT223-0046067-IPC_A 1300,1105 r0 top
U8 "AD5689RTCPZ-EP-RL7" FP-CP-16-22-IPC_C 1094.53,-515.25 r180 top
U9 "ADA4940" ADA4940-Footprint-1 2875.1,-590.16 r180 top
U10 "LTC1563-2CGN#PBF" LTC1563-2CGN#PBF-Footprint-1 2560,52.5 r0 top
U11 "LTC1563-2CGN#PBF" LTC1563-2CGN#PBF-Footprint-1 5143,57.5 r0 top
U12 "LTC1563-2CGN#PBF" LTC1563-2CGN#PBF-Footprint-1 3485,47.5 r0 top
U13 "LTC1563-2CGN#PBF" LTC1563-2CGN#PBF-Footprint-1 4305,52.5 r0 top

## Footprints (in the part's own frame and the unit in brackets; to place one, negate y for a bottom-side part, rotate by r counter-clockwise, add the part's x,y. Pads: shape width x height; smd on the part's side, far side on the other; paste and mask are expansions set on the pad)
61302011821 [mm] "Socket Header, Pitch 2.54 mm, THT, Vertical, single row, 20p"
  rrect50% 1.52x1.52 hole 1.02: 1(-24.13,0)
  round 1.52 hole 1.02: 2(-21.59,0) 3(-19.05,0) 4(-16.51,0) 5(-13.97,0) 6(-11.43,0) 7(-8.89,0) 8(-6.35,0) 9(-3.81,0) 10(-1.27,0) 11(1.27,0) 12(3.81,0) 13(6.35,0) 14(8.89,0) 15(11.43,0) 16(13.97,0) 17(16.51,0) 18(19.05,0) 19(21.59,0) 20(24.13,0)
  silkscreen extent -26.39,-1.35 25.78,1.35, body extent -25.65,-1.25 25.65,1.25, height 8.55
ADA4940-Footprint-1 [mil]
  rect 10.81x31.68 smd paste+0 mask+0: 1(44.21,59.9) 2(24.53,59.9) 3(4.84,59.9) 4(-14.84,59.9) 5(-34.53,59.9) 6(-54.21,59.9) 13(-54.21,-89.9) 14(-34.53,-89.9) 15(-14.84,-89.9) 16(4.84,-89.9) 17(24.53,-89.9) 18(44.21,-89.9)
  rect 31.68x10.81 smd paste+0 mask+0: 7(-79.9,34.21) 8(-79.9,14.53) 9(-79.9,-5.16) 10(-79.9,-24.84) 11(-79.9,-44.53) 12(-79.9,-64.21) 19(69.9,-64.21) 20(69.9,-44.53) 21(69.9,-24.84) 22(69.9,-5.16) 23(69.9,14.53) 24(69.9,34.21)
  rect 104.33x104.33 smd paste+0 mask+0: HTAB(-5,-15)
  silkscreen extent -89,-99 79,69, body extent -84,-94 74,64, height 39
ADI-CP-32-2_L [mm] "QFN, 32-Leads, Body 5x5mm, Pitch 0.5mm, Thermal Pad 3.1x3.1mm, IPC High Density"
  oval 0.8x0.25 smd: 1(-2.4,1.75) 2(-2.4,1.25) 3(-2.4,0.75) 4(-2.4,0.25) 5(-2.4,-0.25) 6(-2.4,-0.75) 7(-2.4,-1.25) 8(-2.4,-1.75) 17(2.4,-1.75) 18(2.4,-1.25) 19(2.4,-0.75) 20(2.4,-0.25) 21(2.4,0.25) 22(2.4,0.75) 23(2.4,1.25) 24(2.4,1.75)
  oval 0.25x0.8 smd: 9(-1.75,-2.4) 10(-1.25,-2.4) 11(-0.75,-2.4) 12(-0.25,-2.4) 13(0.25,-2.4) 14(0.75,-2.4) 15(1.25,-2.4) 16(1.75,-2.4) 25(1.75,2.4) 26(1.25,2.4) 27(0.75,2.4) 28(0.25,2.4) 29(-0.25,2.4) 30(-0.75,2.4) 31(-1.25,2.4) 32(-1.75,2.4)
  rect 3.1x3.1 smd: 33(0,0)
  silkscreen extent -3.47,-2.7 2.7,2.7, body extent -2.55,-2.55 2.55,2.55, height 1
CAPC0603(1608)100_L [mm] "Chip Capacitor, Body 1.6x0.8mm, Height 1.0mm, IPC High Density"
  rect 0.7x0.9 smd: 1(-0.7,0) 2(0.7,0)
  silkscreen extent -0.05,-0.35 0.05,0.35, body extent -0.87,-0.47 0.88,0.48, height 1
CAPC0603(1608)100_M [mm] "Chip Capacitor, Body 1.6x0.8mm, Height 1.0mm, IPC Low Density"
  rect 1.1x1.1 smd: 1(-0.9,0) 2(0.9,0)
  silkscreen extent -0.05,-0.45 0.05,0.45, body extent -0.87,-0.47 0.88,0.48, height 1
CAPC0603(1608)100_N [mm] "Chip Capacitor, Body 1.6x0.8mm, Height 1.0mm, IPC Medium Density"
  rect 0.9x1 smd: 1(-0.8,0) 2(0.8,0)
  silkscreen extent -0.05,-0.4 0.05,0.4, body extent -0.87,-0.48 0.88,0.47, height 1
CAPC1608X87X35LL15T15 [mm] "Chip Capacitor, 2-Leads, Body 1.60x0.80mm, IPC High Density"
  rect 0.8x0.9 smd: 1(-0.625,0) 2(0.625,0)
  body extent -0.87,-0.48 0.87,0.48, height 0.87
CAPC1608X90X35LL15T15 [mm] "Chip Capacitor, 2-Leads, Body 1.60x0.81mm, IPC High Density"
  rect 0.85x0.9 smd: 1(-0.65,0) 2(0.65,0)
  body extent -0.88,-0.48 0.87,0.48, height 0.9
CAPC1608X92X38LL15T08 [mm] "Chip Capacitor, 2-Leads, Body 1.60x0.80mm, IPC High Density"
  rect 0.75x0.9 smd: 1(-0.625,0) 2(0.625,0)
  body extent -0.87,-0.48 0.87,0.48, height 0.92
CAPC1608X92X38NL15T08 [mm] "Chip Capacitor, 2-Leads, Body 1.60x0.80mm, IPC Medium Density"
  rect 0.85x1 smd: 1(-0.675,0) 2(0.675,0)
  body extent -0.87,-0.48 0.87,0.47, height 0.92
CAPC1608X95X40LL15T15 [mm] "Chip Capacitor, 2-Leads, Body 1.60x0.80mm, IPC High Density"
  rect 0.85x0.9 smd: 1(-0.6,0) 2(0.6,0)
  body extent -0.87,-0.48 0.88,0.48, height 0.95
CAPC1608X95X40ML15T15 [mm] "Chip Capacitor, 2-Leads, Body 1.60x0.80mm, IPC Low Density"
  rect 1.05x1.1 smd: 1(-0.7,0) 2(0.7,0)
  body extent -0.88,-0.48 0.87,0.47, height 0.95
CAPC1608X95X40NL15T15 [mm] "Chip Capacitor, 2-Leads, Body 1.60x0.80mm, IPC Medium Density"
  rect 0.95x1 smd: 1(-0.65,0) 2(0.65,0)
  body extent -0.88,-0.48 0.87,0.47, height 0.95
CONN_SMA-J-P-H-RA-TH1_SAI [mil]
  round 83 / inner round 60 / far side round 83 hole 63 paste-99999 mask+0: 1(0,0) 2(-100,100) 3(-100,-100) 4(100,-100) 5(100,100)
  silkscreen extent -143,-143 191,466
DEA142450BT3028A1 [mm]
  rect 0.25x0.325 smd: 1(-0.5,0) 2(0,-0.287) 3(0.5,-0.287) 4(0.5,0.288) 5(0,0.288)
  silkscreen extent -1.2,-0.05 -1.1,0.05
DLF0004A_MFG [mm] "Recommended Land Pattern"
  rrect15% 0.9x0.65 smd: 1(-0.75,0.825) 2(-0.75,-0.825) 3(0.75,-0.825) 4(0.75,0.825)
  silkscreen extent -1.87,-0.13 1.05,0.95, body extent -1.3,-1.4 1.3,1.4, height 0.25
FP-BLM18-0_15-t0_8-IPC_B [mil]
  rect 43.55x37.73 smd paste+0 mask+0: 1(-26.62,0) 2(26.62,0)
  silkscreen extent -48,-35 48,35, body extent -58,-29 58,29, height 10
FP-C0402C102K4RAC7411-MFG [mm]
  rect 0.52x0.52 smd paste+0 mask+0: 1(-0.4,0) 2(0.4,0)
  silkscreen extent -0.5,-0.63 0.5,0.64, body extent -0.8,-0.4 0.8,0.4, height 0.25
FP-C1206C-EB-MFG [mm]
  rect 0.95x1.7 smd paste+0 mask+0: 1(-1.4,0) 2(1.4,0)
  silkscreen extent -0.55,-0.9 0.55,0.9, body extent -2,-1 2,1, height 0.25
FP-C1608-080-0_1-IPC_C [mil]
  rect 36.66x31.97 smd paste+0 mask+0: 1(-21.28,0) 2(21.28,0)
  silkscreen extent -40,-33 40,33, body extent -44,-22 44,22, height 10
FP-C2012-125-0_2-IPC_A [mil]
  rect 62.13x61.27 smd paste+0 mask+0: 1(-34.02,0) 2(34.02,0)
  silkscreen extent -65,-46 65,46, body extent -85,-50 85,50, height 10
FP-CGA2B-IPC_B [mm]
  rect 0.372x0.572 smd paste+0 mask+0: 1(-0.55,0) 2(0.55,0)
  silkscreen extent -0.74,-0.69 0.74,0.69, body extent -0.89,-0.44 0.89,0.44, height 0.25
FP-CGA2B-MFG [mm]
  rect 0.4x0.5 smd paste+0 mask+0: 1(-0.4,0) 2(0.4,0)
  silkscreen extent -0.53,-0.62 0.53,0.62, body extent -0.7,-0.38 0.7,0.38, height 0.25
FP-CGA3E-0_3-0_1-IPC_A [mm]
  rect 0.956x1.206 smd paste+0 mask+0: 1(-1.025,0) 2(1.025,0)
  silkscreen extent -0.25,-0.6 0.25,0.6, body extent -2,-1.1 2,1.1, height 0.25
FP-CGA5L-0_3-0_1-IPC_A [mm]
  rect 0.956x2.006 smd paste+0 mask+0: 1(-1.825,0) 2(1.825,0)
  silkscreen extent -1.05,-1 1.05,1, body extent -2.8,-1.5 2.8,1.5, height 0.25
FP-CGA5L-MFG [mm]
  rect 1.1x1.35 smd paste+0 mask+0: 1(-1.65,0) 2(1.65,0)
  silkscreen extent -0.73,-0.9 0.73,0.9, body extent -2.3,-1 2.3,1, height 0.25
FP-CP-16-22-IPC_C [mm]
  rect 0.731x0.239 smd paste+0 mask+0: 1(-1.391,0.75)
  rrect100% 0.731x0.239 smd paste+0 mask+0: 2(-1.391,0.25) 3(-1.391,-0.25) 4(-1.391,-0.75) 9(1.391,-0.75) 10(1.391,-0.25) 11(1.391,0.25) 12(1.391,0.75)
  rrect100% 0.239x0.731 smd paste+0 mask+0: 5(-0.75,-1.391) 6(-0.25,-1.391) 7(0.25,-1.391) 8(0.75,-1.391) 13(0.75,1.391) 14(0.25,1.391) 15(-0.25,1.391) 16(-0.75,1.391)
  rect 1.75x1.75 smd paste-1000 mask+0: 17(0,0)
  silkscreen extent -2.28,-1.5 1.5,1.5, body extent -1.86,-1.86 1.86,1.86, height 0.25
FP-CPF0603-MFG [mm]
  rect 1x0.9 smd paste+0 mask+0: 1(-0.9,0) 2(0.9,0)
  silkscreen extent -0.83,-0.82 0.82,0.82, body extent -1.5,-0.55 1.5,0.55, height 0.25
FP-CR0603-IPC_A [mil]
  rect 45.6x39.85 smd paste+0 mask+0: 1(-32.56,0) 2(32.56,0)
  silkscreen extent -55,-36 55,36, body extent -75,-40 75,40, height 10
FP-CR0603-IPC_B [mil]
  rect 37.72x35.91 smd paste+0 mask+0: 1(-28.62,0) 2(28.62,0)
  silkscreen extent -47,-34 47,34, body extent -57,-28 57,28, height 10
FP-CRCW0402-e3-IPC_C [mil]
  rect 18.43x18.6 smd paste+0 mask+0: 1(-15.83,0) 2(15.83,0)
  silkscreen extent -25,-27 25,27, body extent -29,-15 29,15, height 10
FP-CRCW0603-e3-IPC_B [mil]
  rect 36.81x37.88 smd paste+0 mask+0: 1(-28.17,0) 2(28.17,0)
  silkscreen extent -30,-37 30,35, body extent -56,-29 56,29, height 10
FP-CRCW0603-e3-IPC_C [mil]
  rect 28.94x33.94 smd paste+0 mask+0: 1(-24.23,0) 2(24.23,0)
  silkscreen extent -30,-33 30,33, body extent -43,-23 43,23, height 10
FP-CRG0402-IPC_B [mil]
  rect 25.97x22.54 smd paste+0 mask+0: 1(-16.78,0) 2(16.78,0)
  silkscreen extent -30,-27 30,27, body extent -36,-17 36,17, height 10
FP-CRGCQ0603-IPC_A [mil]
  rect 45.6x39.85 smd paste+0 mask+0: 1(-32.56,0) 2(32.56,0)
  silkscreen extent -55,-36 55,36, body extent -75,-40 75,40, height 10
FP-CRGCQ0603-IPC_C [mil]
  rect 29.85x31.97 smd paste+0 mask+0: 1(-24.68,0) 2(24.68,0)
  silkscreen extent -40,-33 40,33, body extent -44,-22 44,22, height 10
FP-DLW5BS-MFG [mil]
  round 34.99 smd paste+0 mask+0: 1(-37.16,-63.24) 4(-37.16,46.51)
  round 35.31 smd paste+0 mask+0: 2(38.63,-71.6) 3(38.63,71.6)
  Top Layer region: -108.27,-92.52 -17.72,-92.52 -17.72,-25.59 -57.09,-25.59 -57.09,-64.96 -108.27,-64.96 -108.27,-92.52
  Top Layer region: 108.27,-92.52 17.72,-92.52 17.72,-25.59 57.09,-25.59 57.09,-64.96 108.27,-64.96 108.27,-92.52
  Top Layer region: 108.27,92.52 17.72,92.52 17.72,25.59 57.09,25.59 57.09,64.96 108.27,64.96 108.27,92.52
  Top Layer region: -108.27,92.52 -17.72,92.52 -17.72,25.59 -57.09,25.59 -57.09,64.96 -108.27,64.96 -108.27,92.52
  silkscreen extent -136,-114 104,114, body extent -112,-108 112,108, height 10
FP-GCJ21B-0_3-IPC_A [mil]
  rect 61.16x61.27 smd paste+0 mask+0: 1(-36.43,0) 2(36.43,0)
  silkscreen extent -67,-46 67,46, body extent -87,-50 87,50, height 10
FP-GCM21B-0_15-IPC_A [mil]
  rect 55.34x59.38 smd paste+0 mask+0: 1(-36.47,0) 2(36.47,0)
  silkscreen extent -64,-45 64,45, body extent -84,-49 84,49, height 10
FP-GCM155-0_05-IPC_A [mil]
  rect 28.16x26.48 smd paste+0 mask+0: 1(-18.84,0) 2(18.84,0)
  silkscreen extent -33,-29 33,29, body extent -41,-21 41,21, height 10
FP-GQM187-0_15-IPC_C [mil]
  rect 31.75x33.79 smd paste+0 mask+0: 1(-24.64,0) 2(24.64,0)
  silkscreen extent -41,-34 41,34, body extent -44,-23 44,23, height 10
FP-GRM31C-0_2-e0_3_0_8-IPC_B [mil]
  rect 53.33x71.11 smd paste+0 mask+0: 1(-54.16,0) 2(54.16,0)
  silkscreen extent -16,-36 16,36, body extent -91,-45 91,45, height 10
FP-GRM188-0_1-e0_2_0_5-IPC_B [mil]
  rect 37.74x35.91 smd paste+0 mask+0: 1(-28.61,0) 2(28.61,0)
  silkscreen extent -47,-34 47,34, body extent -57,-28 57,28, height 10
FP-LQG15HH_02-MFG [mm]
  rect 0.4x0.5 smd paste+0 mask+0: 1(-0.4,0) 2(0.4,0)
  silkscreen extent -1.27,-0.64 0.53,0.65, body extent -0.7,-0.38 0.7,0.38, height 0.25
FP-LQG15WH_02-MFG [mm]
  rect 0.35x0.65 smd paste+0 mask+0: 1(-0.425,0) 2(0.425,0)
  silkscreen extent -1.28,-0.78 0.53,0.73, body extent -0.7,-0.43 0.7,0.43, height 0.25
FP-LQW18CA_00-MFG [mm]
  rect 0.75x1 smd paste+0 mask+0: 1(-0.725,0) 2(0.725,0)
  silkscreen extent -0.87,-0.9 0.87,0.9, body extent -1.2,-0.6 1.2,0.6, height 0.25
FP-MCT0603-IPC_B [mil]
  rect 34x37.88 smd paste+0 mask+0: 1(-28.72,0) 2(28.72,0)
  silkscreen extent -46,-35 46,35, body extent -56,-29 56,29, height 10
FP-RK-3-MFG [mm]
  rect 0.86x1.27 smd paste+0 mask+0: 1(-1.5,-2.278) 3(1.5,-2.278)
  round 1.62 smd paste+0 mask+0: 2(0,0.164)
  Top Layer region: -0.9,2.458 0.9,2.458 0.9,-1.022 0.43,-1.022 0.43,-2.913 -0.43,-2.913 -0.43,-1.022 -0.9,-1.022
  silkscreen extent -2.3,-1.3 2.3,1.3, body extent -2.4,-3.01 2.4,2.56, height 0.25
FP-RMCF0603-IPC_B [mil]
  rect 39.61x37.73 smd paste+0 mask+0: 1(-27.6,0) 2(27.6,0)
  silkscreen extent -47,-35 47,35, body extent -57,-29 57,29, height 10
FP-RT0402-MFG [mm]
  rect 0.5x0.6 smd paste+0 mask+0: 1(-0.5,0) 2(0.5,0)
  silkscreen extent -0.5,-0.71 0.5,0.7, body extent -0.85,-0.4 0.85,0.4, height 0.25
FP-SOT223-0046067-IPC_A [mm]
  rect 2.204x0.96 smd paste+0 mask+0: 1(-3.1,2.3)
  rrect100% 2.204x0.96 smd paste+0 mask+0: 2(-3.1,0) 3(-3.1,-2.3)
  rrect44% 2.204x3.26 smd paste+0 mask+0: 4(3.1,0)
  silkscreen extent -5.85,-3.25 1.75,3.25, body extent -4.7,-3.75 4.7,3.75, height 0.25
FP-SR0603-MFG [mm]
  rect 0.9x0.8 smd paste+0 mask+0: 1(-0.85,0) 2(0.85,0)
  silkscreen extent -0.02,-0.45 0.02,0.45, body extent -1.4,-0.55 1.4,0.55, height 0.25
FP-TSW-102-07-G-S-MFG [mm]
  rect 1.57x1.57 hole 1.02 paste-2539.97 mask+0: 1(-1.27,0)
  round 1.57 hole 1.02 paste-2539.97 mask+0: 2(1.27,0)
  silkscreen extent -3.42,-1.34 2.73,1.34, body extent -2.83,-1.44 2.83,1.44, height 0.25
FP-TSW-102-07-L-S-MFG [mm]
  rect 1.57x1.57 hole 1.02 paste-2539.97 mask+0: 1(-1.27,0)
  round 1.57 hole 1.02 paste-2539.97 mask+0: 2(1.27,0)
  silkscreen extent -3.25,-1.34 2.73,1.34, body extent -2.83,-1.44 2.83,1.44, height 0.25
FP-VJ0603Y105KXJCW1BC-MFG [mm]
  rect 0.8x0.8 smd paste+0 mask+0: 1(-0.75,0) 2(0.75,0)
  silkscreen extent -0.87,-0.78 0.87,0.78, body extent -1.28,-0.7 1.28,0.7, height 0.25
LTC1563-2CGN#PBF-Footprint-1 [mil]
  rect 78x14 smd paste+0 mask+0: 1(-87,82.5) 2(-87,57.5) 3(-87,32.5) 4(-87,7.5) 5(-87,-17.5) 6(-87,-42.5) 7(-87,-67.5) 8(-87,-92.5) 9(107,-92.5) 10(107,-67.5) 11(107,-42.5) 12(107,-17.5) 13(107,7.5) 14(107,32.5) 15(107,57.5) 16(107,82.5)
  silkscreen extent -38,-108 166,98, body extent -112,-103 132,93, height 67
QFN50P400X400X100-25N-D [mm]
  rect 0.85x0.3 smd: 1(-1.95,1.25) 2(-1.95,0.75) 3(-1.95,0.25) 4(-1.95,-0.25) 5(-1.95,-0.75) 6(-1.95,-1.25) 13(1.95,-1.25) 14(1.95,-0.75) 15(1.95,-0.25) 16(1.95,0.25) 17(1.95,0.75) 18(1.95,1.25)
  rect 0.3x0.85 smd: 7(-1.25,-1.95) 8(-0.75,-1.95) 9(-0.25,-1.95) 10(0.25,-1.95) 11(0.75,-1.95) 12(1.25,-1.95) 19(1.25,1.95) 20(0.75,1.95) 21(0.25,1.95) 22(-0.25,1.95) 23(-0.75,1.95) 24(-1.25,1.95)
  rect 2.55x2.55 smd: 25(0,0)
  silkscreen extent -2.5,1.88 -2.25,2.12
RESC1609X50X30LL10T20 [mm] "Chip Resistor, 2-Leads, Body 1.55x0.85mm, IPC High Density"
  rect 0.7x0.85 smd: 1(-0.575,0) 2(0.575,0)
  body extent -0.82,-0.48 0.82,0.48, height 0.5
RESC1609X50X30NL10T20 [mm] "Chip Resistor, 2-Leads, Body 1.55x0.85mm, IPC Medium Density"
  rect 0.8x0.95 smd: 1(-0.625,0) 2(0.625,0)
  body extent -0.82,-0.48 0.82,0.48, height 0.5
RESC1609X55X30NL10T20 [mm] "Chip Resistor, 2-Leads, Body 1.60x0.85mm, IPC Medium Density"
  rect 0.95x0.95 smd: 1(-0.725,0) 2(0.725,0)
  body extent -0.85,-0.48 0.85,0.48, height 0.55
SMTC-TSW-106-07-S-S_V [mm] "Header, 6-Leads, Body 15.24x2.54mm, Pitch 2.54mm"
  rect 1.55x1.55 hole 1.02: 1(-6.35,0)
  round 1.55 hole 1.02: 2(-3.81,0) 3(-1.27,0) 4(1.27,0) 5(3.81,0) 6(6.35,0)
  silkscreen extent -7.62,-1.27 7.62,2.04, body extent -7.62,-1.27 7.75,1.27, height 8.38

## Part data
BPF1: library part CMP-034-000001-3, "Signal Conditioning LTCC BAND PASS FLTR 2400-2500MHz", Cutoff Frequency=2.45GHz, Manufacturer Lifecycle Status=PRODUCTION, Manufacturer_Name=TDK, Max Operating Temperature=85°C, Min Operating Temperature=-40°C, Mouser Part Number=810-DEA142450BT30281
C1 C6 C7 C12 C13 C14 C23 C24 C25 C30 C31 C36 C37 C42 C92 C95: library part CMP-2006-01631-1, "Ceramic Capacitor, Multilayer, Ceramic, 16V, 20% +Tol, 20% -Tol, X7R, 15% TC, 0.1uF, Surface Mount, 0603", Manufacturer=Vitramon, Part Number=VJ0603Y104MXJPW1BC
C2 C5 C8 C11 C15 C18 C19 C22 C26 C29 C32 C35 C38 C41 C93 C94 C102: library part CMP-00075-1, "0805 10 uF 6.3 V ±10% Tolerance X7R Multilayer Ceramic Chip Capacitor", Case/Package=0805, Dielectric=X7R, Dielectric Material=Ceramic, Manufacturer Lifecycle Status="IN PRODUCTION", Max Operating Temperature=125°C, Min Operating Temperature=-55°C, Tolerance=10%, Voltage Rating=6.3V
C3 C9 C16 C20 C27 C33 C39: library part CMP-00030-45106517-1, "VJ0603Y105KXJCW1BC Multilayer Ceramic Capacitor, 1 uF, 16 V, ± 10%, X7R, 0603 [1608 Metric]", Capacitance=1µF, Case/Package=0603, Dielectric=X7R, Dielectric Material=Tantalum, Max Operating Temperature=125°C, Min Operating Temperature=-55°C, Tolerance=10%, Voltage Rating=16V
C4 C10 C17 C21 C28 C34 C40: library part CMP-06035-051513-1, "Multilayer Ceramic Capacitors MLCC - SMD/SMT 0805 4.7uF 10%, 16VDC,  X7R 15%", Capacitance=4.7uF, Case Code (Imperial)=0805, Case Code (Metric)=2012, Dielectric=X7R, Max Operating Temperature=125°C, Min Operating Temperature=-55°C, Package Quantity=10000, Tolerance=10%, Voltage Rating (DC)=16V
C43 C44 C46 C51 C52 C59 C60 C64 C66 C70 C72: library part CMP-00023-1, "Ceramic Capacitor, Multilayer, Ceramic, 25V, 10% +Tol, 10% -Tol, X7R, 15% TC, 0.1uF, Surface Mount, 0603"
C45 C49 C50 C57 C58 C63 C65 C69 C71: library part CMP-1035-02796-1, "CAP 10uF 6.3V ±10% 0603 (1608 Metric) Thickness 1mm SMD", Case-EIA=0603, Case-Metric=1608, Rated Voltage="6.3 V", Tolerance=Â±10%
C47 C48: library part CMP-2006-04266-1, "200pF", Manufacturer="AVX Interconnect / Elco", Part Number=06035A201FAT2A
C53 C54 C55 C56 C61 C62 C67 C68: library part CMP-00052-1, "CGA Series 1206 100 nF 50 V ±5 % Tolerance C0G SMT Multilayer Ceramic Capacitor"
C73 C76: library part CMP-03020-021251-2, "CAP CER 1000PF 16V X7R 0402", Case Code (Imperial)=0402, Case Code (Metric)=1005, Dielectric=X7R, Dielectric Material=Ceramic, Max Operating Temperature=125°C, Min Operating Temperature=-55°C, Tolerance=10%, Voltage Rating=16V
C74 C81: library part CMP-08246-000350-1, "Cap Ceramic 2.2pF 50V C0G 0.25pF Pad SMD 0402 +125°C Automotive T/R", Case Code (Imperial)=0402, Case Code (Metric)=1005, Dielectric=C0G, Max Operating Temperature=125°C, Min Operating Temperature=-55°C, Package Quantity=1, Ratings=AEC-Q200, Voltage Rating=50V
C75: library part CMP-06035-012333-1, "Ceramic Capacitor for Automotive 1.5pF ±5% 50VDC C0G 0402 Paper T/R", Case Code (Imperial)=0402, Case Code (Metric)=1005, Max Operating Temperature=125°C, Min Operating Temperature=-55°C, Ratings=AEC-Q200, Tolerance=5%, Voltage Rating=50V
C77 C78: library part CMP-2006-01663-1, Manufacturer=Vitramon, Part Number=VJ0603A102JXXCW1BC
C79 C80: library part CMP-08246-001196-1, "Cap Ceramic 1nF 250V C0G 5% Pad SMD 0603 +125°C Automotive T/R", Case Code (Imperial)=0603, Case Code (Metric)=1608, Dielectric=C0G, Max Operating Temperature=125°C, Min Operating Temperature=-55°C, Package Quantity=4000, Ratings=AEC-Q200, Tolerance=5%, Voltage Rating=250V
C82: library part CMP-08246-001768-1, "Cap Ceramic 1.5pF 50V C0G 0.25pF Pad SMD 0402 +125°C Automotive T/R", Case Code (Imperial)=0402, Case Code (Metric)=1005, Dielectric=C0G, Max Operating Temperature=125°C, Min Operating Temperature=-55°C, Package Quantity=1, Ratings=AEC-Q200, Voltage Rating=50V
C83 C85: library part CMP-06035-003994-1, "Chip Multilayer Ceramic Capacitors for General Purpose, 1206, 0.10uF, C0G, 30ppm/°C, 5%, 50V", Case Code (Imperial)=1206, Case Code (Metric)=3216, Dielectric=C0G, Max Operating Temperature=125°C, Min Operating Temperature=-55°C, Package Quantity=1, Temperature Coefficient=30ppm/°C, Tolerance=5%, Voltage=50V
C84 C86 C90: library part CMP-2006-01151-1, Manufacturer=Vitramon, Part Number=VJ0603A100JXBAC
C87: library part CMP-08246-005643-1, "Multilayer Ceramic Capacitors 2.7nF ±5% 250V C0G SMD 0805", Case Code (Imperial)=0805, Case Code (Metric)=2012, Dielectric=C0G, Max Operating Temperature=125°C, Min Operating Temperature=-55°C, Package Quantity=2000, Tolerance=5%, Voltage Rating=250V
C88: library part CMP-03020-008489-1, "C1206 39,000 pF C0G 5.00% 50 V", Capacitance="39,000 pF", Manufacturer=KEMET, Manufacturer Part Number=C1206C393J5GACTU, Package=C1206C-EB, Temperature="-55°C to +150°C", Temperature Characteristic=C0G, Temperature Coefficient=15%, Temperature Range High=+150°C, Temperature Range Low=-55°C, Tolerance=0.05, Voltage Rating="50 V"
C89: library part CMP-08246-006367-1, "Multilayer Ceramic Capacitors 1.2nF ±5% 100V C0G SMD 0603", Case Code (Imperial)=0603, Case Code (Metric)=1608, Dielectric=C0G, Max Operating Temperature=125°C, Min Operating Temperature=-55°C, Package Quantity=4000, Tolerance=5%, Voltage Rating=100V
C91: library part CMP-08246-001706-1, "Cap Ceramic 100nF 100V C0G 5% Pad SMD 1206 +125°C Automotive T/R", Case Code (Imperial)=1206, Case Code (Metric)=3216, Dielectric=C0G, Max Operating Temperature=125°C, Min Operating Temperature=-55°C, Package Quantity=2000, Ratings=AEC-Q200, Tolerance=5%, Voltage Rating=100V
C96 C98 C101 C103: library part CMP-2006-01799-1, Manufacturer=Vitramon, Part Number=VJ0603A120KXJCW1BC
C97: library part CMP-1035-00425-1, "CAP 6.8pF 16V ±0.5pF 0603 (1608 Metric) Thickness 1mm SMD", Case-EIA=0603, Case-Metric=1608, Rated Voltage="16 V", Tolerance=Â±0.5pF
C99: library part CMP-06035-025553-1, "Ceramic Capacitor 0.2pF ±0.1pF 250VDC C0G 0603 Paper T/R", Capacitance=0.2pF, Case Code (Imperial)=0603, Case Code (Metric)=1608, Dielectric=C0G, Max Operating Temperature=125°C, Min Operating Temperature=-55°C, Package Quantity=4000, Voltage Rating=250V
C100: library part CMP-2006-02556-2, "Chip Multilayer Ceramic Capacitors for General Purpose, 0603, 10000pF, C0G, 30ppm/°C, 5%, 50V", Capacitance=10nF, Case Code (Imperial)=0603, Case Code (Metric)=1608, Dielectric=C0G, Max Operating Temperature=125°C, Min Operating Temperature=-55°C, Package Quantity=4000, Tolerance=5%, Voltage=50V
C104: library part CMP-1035-00152-1, "CAP 2.2pF 16V ±0.5pF 0603 (1608 Metric) Thickness 1mm SMD", Case-EIA=0603, Case-Metric=1608, Rated Voltage="16 V", Tolerance=Â±0.5pF
C105: library part CMP-2006-01498-1, Manufacturer=Vitramon, Part Number=VJ0603D1R2BXPAJ
C106: library part CMP-2006-00028-1, Manufacturer=Vitramon, Part Number=VJ0603A1R0CXACW1BC
FB1 FB2 FB3 FB4 FB5 FB6 FB7: library part CMP-06046-002207-1, "Chip Ferrite Bead, 0603, 180Ω @ 100MHz, 0.09Ω, 25%, 1.5A"
IQM1: library part CMP-004-000002-1, "TRF3705IRGET, Modulator Quadrature 3.1dB 3.15  3.6 V 24-Pin VQFN", Manufacturer_Name="Texas Instruments", Mouser Part Number=595-TRF3705IRGET
J1 J6 J7: library part CMP-02766-000084-1, "CONN HEADER VERT 2POS 2.54MM", Current Rating=6.3A, Manufacturer=Samtec, Temperature="-55°C to +125°C", Temperature Range High=+125°C, Temperature Range Low=-55°C, Voltage Rating=550V
J2 J3: library part CMP-1681-00007-2, "Male Header, Pitch 2.54 mm, 1 x 6 Position, Height 8.38 mm, Tail Length 2.54 mm, -55 to 125 degC, RoHS, Bulk", Colour=Black, Manufacturer=Samtec, Max Operating Temperature="125 degC", Min Operating Temperature="-55 degC", Package Quantity=1
J4: library part CMP-02766-001428-1, "CONN HEADER VERT 2POS 2.54MM", Color=Black, Current Rating=7.6A, Max Operating Temperature=125°C, Max Voltage Rating (AC)=550V, Min Operating Temperature=-55°C, Package Quantity=1
J5: library part CMP-009-000000-1, "Description", Manufacturer_Name="Samtec Inc"
J8 J9: library part CMP-1502-01348-4, "THT Vertical Socket Header WR-PHD, Pitch 2.54 mm, Single Row, 20 pins", Contact Resistance=20mΩ, Current Rating=3A, Operating Supply Voltage=250V
L1 L2 L3 L4 L5 L6 L7: library part CMP-00050-1, "Common Mode Chokes Dual 500Ohm 100MHz 1A 0.23Ohm DCR SMD T/R", Case/Package=2020, Current Rating=1A, DC Resistance (DCR)=230mΩ, Insulation Resistance=10MΩ, Max Operating Temperature=105°C, Min Operating Temperature=-40°C, Test Frequency=100MHz, Tolerance=40%, Voltage Rating=50V
L8 L11: library part CMP-06042-009995-1, "Multilayer type RF Inductor 3.6nH ±0.2nH 0.14Ω 750mA 0402", Case/Package=0402, Current Rating=750mA, DC Resistance (DCR)=140mR, Max Operating Temperature=125°C, Min Operating Temperature=-55°C, Self Resonant Frequency=6GHz, Test Frequency=100MHz
L9 L10: library part CMP-06042-014192-1, "Multilayer type Inductor for Automotive 7.5nH ±3% 0.16Ω 600mA 0402", Case Code (Imperial)=0402, Case Code (Metric)=1005, Current Rating=600mA, DC Resistance (DCR)=160mR, Max Operating Temperature=125°C, Min Operating Temperature=-55°C, Ratings=AEC-Q200, Self Resonant Frequency=4GHz, Test Frequency=100MHz, Tolerance=3%
L12: library part CMP-06042-003325-1, "Wire Wound Ferrite type RF Inductor 15nH ±5% 2200mA 0.025Ω 0603 (1608)", Case Code (Imperial)=0603, Case Code (Metric)=1608, Current Rating=2.2A, DC Resistance (DCR)=25mR, Inductance=15nH, Inductance Tolerance=5%, Max Operating Temperature=85°C, Min Operating Temperature=-40°C, Package Quantity=4000, Resistor Type=Wirewound, Self Resonant Frequency=2GHz, Test Frequency=10MHz
OSC1: library part CMP-00370-145325626-1, "IC 100 MHz LVCMOS Oscillator 1.8V Enable/Disable 4-VDFN", Ambient Temperature Range High=105°C, Frequency=100MHz, Load Capacitance=15pF, Manufacturer Lifecycle Status=ACTIVE, Max Junction Temperature (Tj)=125°C, Max Supply Current=44mA, Max Supply Voltage=1.9V, Min Operating Temperature=-40°C, Min Supply Voltage=1.7V
PA1: library part CMP-09142-000059-1, "IC RF AMP 400MHZ-2.7GHZ SOT89-3", Case/Package=SOT-89, Frequency=400MHz, Max Frequency=2.7GHz, Max Operating Temperature=85°C, Max Power Dissipation=683mW, Max Supply Voltage=5.5V, Min Operating Temperature=-40°C, Min Supply Voltage=3.3V, Nominal Supply Current=104mA, Operating Frequency="400 MHz to 2700 MHz", Operating Supply Voltage=5V, Package Quantity=1, Test Frequency=2.6GHz
PLL1: library part CMP-0287-00013-1, "Wideband Synthesizer with Integrated VCO, CP-32-2, Pb-Free, 1500 Reel", Frequency Range=137.5MHz-4.35GHz, Supply Current=110mA
R1: library part CMP-00035-1, "Res Thick Film 0603 22 Ohm 1% 0.1W(1/10W) ±200ppm/C Pad SMD Automotive T/R"
R2 R3: library part CMP-07231-005094-1, "Thick Film Chip Resistors 0603 2kΩ 0.1W 5% 200ppm/°C", Case Code (Imperial)=0603, Case Code (Metric)=1608, Max Operating Temperature=155°C, Max Power Dissipation=100mW, Min Operating Temperature=-55°C, Package Quantity=10000, Resistance=2kR, Temperature Coefficient=200ppm/°C, Tolerance=5%, Voltage Rating=50V
R4 R7 R8: library part CMP-03211-009884-1, "CRGCQ 0603 10K 5%", Ambient Temperature Range High=+70°C, Manufacturer="TE Connectivity", Manufacturer Part Number=CRGCQ0603J10K, Package=CRGCQ0603, Power Rating=0.1W, Resistance=10KΩ, Temperature="-55°C to +155°C", Temperature Coefficient=±100ppm/°C, Temperature Range High=+155°C, Temperature Range Low=-55°C, Tolerance=0.05, Voltage Rating=75V
R5 R6: library part CMP-26527-006412-1, "0Ω ±0 0.1W 0603 Thick Film Chip Resistor AEC-Q200 compliant", Case/Package=0603, Max Operating Temperature=155°C, Max Power Dissipation=100mW, Min Operating Temperature=-55°C, Resistance=0R, Resistor Type="Thick Film"
R9 R10 R11 R12 R13 R14 R15 R16 R17 R18 R19 R20 R21 R22 R23 R24 R25 R26 R27 R28 R29 R30 R31 R32: library part CMP-00034-1, "Res Thin Film 0603 120K Ohm 0.1% 1/16W ±25ppm/°C Molded SMD SMD Paper T/R"
R33: library part CMP-2000-03826-1, Manufacturer="Vishay Dale", Part Number=CRCW0603100RFKTA
R34: library part CMP-03211-011410-1, "RES SMD 10K OHM 1% 1/16W 0402", Case Code (Imperial)=0402, Max Operating Temperature=125°C, Max Power Dissipation=63mW, Min Operating Temperature=-55°C, Number of Resistors=1, Package Quantity=10000, Resistance=10kR, Resistance Tolerance=1%, Resistor Type="Thick Film", Temperature Coefficient=100ppm/°C, Voltage Rating=50V
R35: library part CMP-2000-03447-2, "RES Thick Film, 51Ω, 5%, 0.1W, 200ppm/°C, 0603", Case Code (Imperial)=0603, Case Code (Metric)=1608, Max Operating Temperature=155°C, Max Power Dissipation=100mW, Min Operating Temperature=-55°C, Package Quantity=1, Resistance=51R, Temperature Coefficient=200ppm/°C, Tolerance=5%, Voltage Rating=75V
R36: library part CMP-2000-03412-1, Manufacturer="Vishay Dale", Part Number=CRCW06034K70FKTA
